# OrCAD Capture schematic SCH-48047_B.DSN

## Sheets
1 Title Page: title: FRDM-KE17Z; rev: B; company: NXP Semiconductors; note: SCH-48047 PDF: SPF-48047; note: 6501 William Cannon Drive West; note: Austin, TX 78735-8598
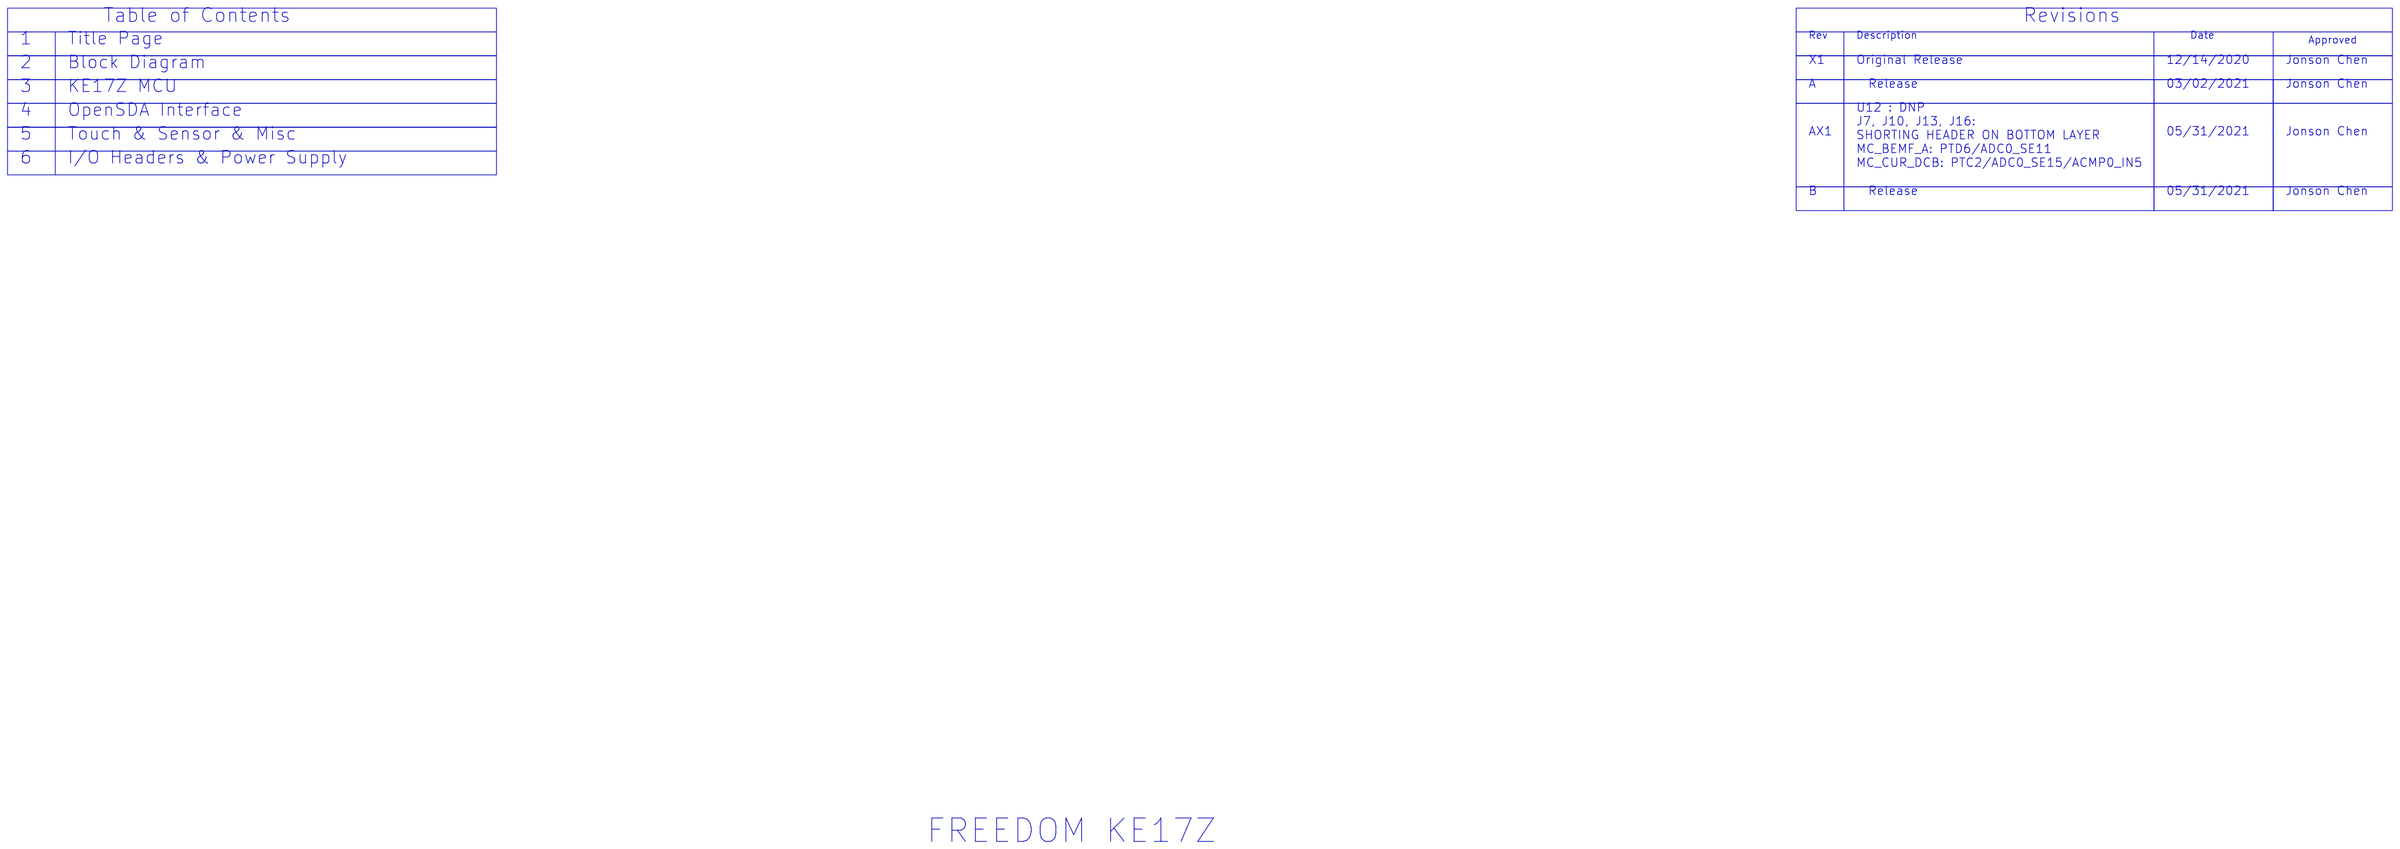
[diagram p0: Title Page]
2 Block Diagram
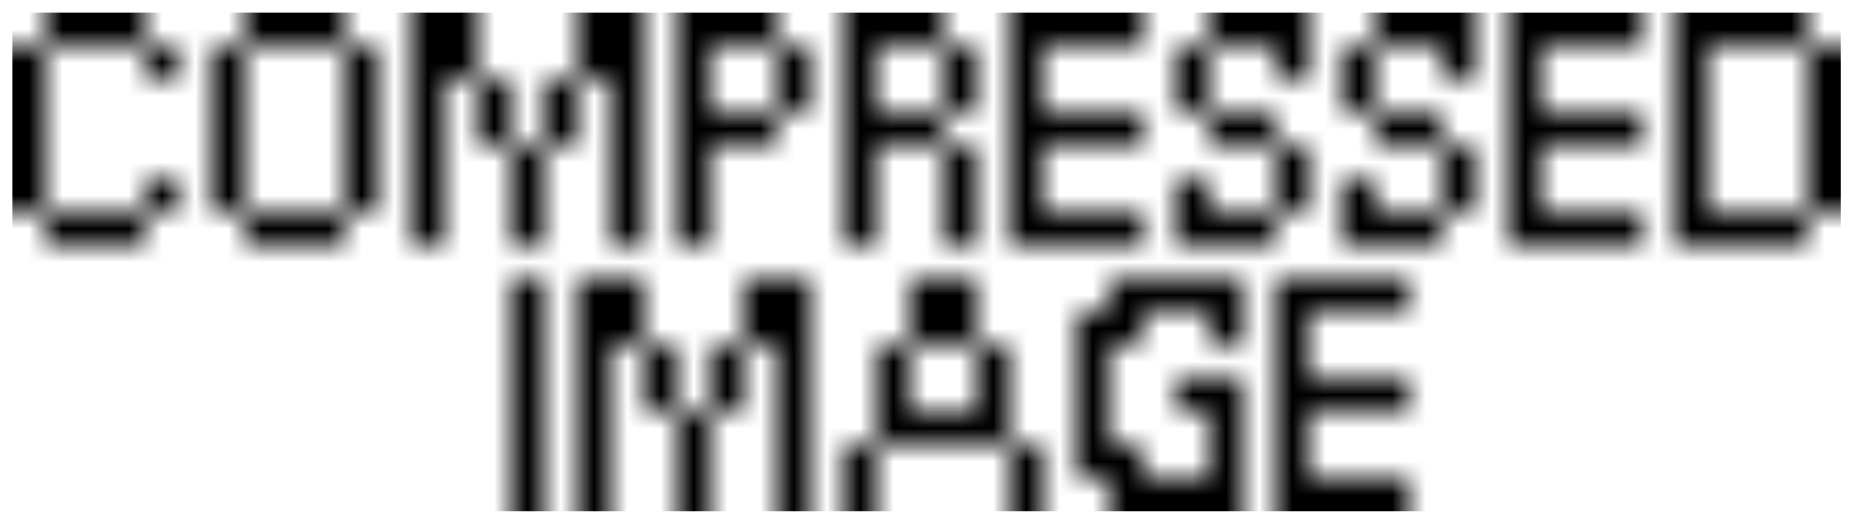
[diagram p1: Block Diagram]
3 KE17Z MCU: size C
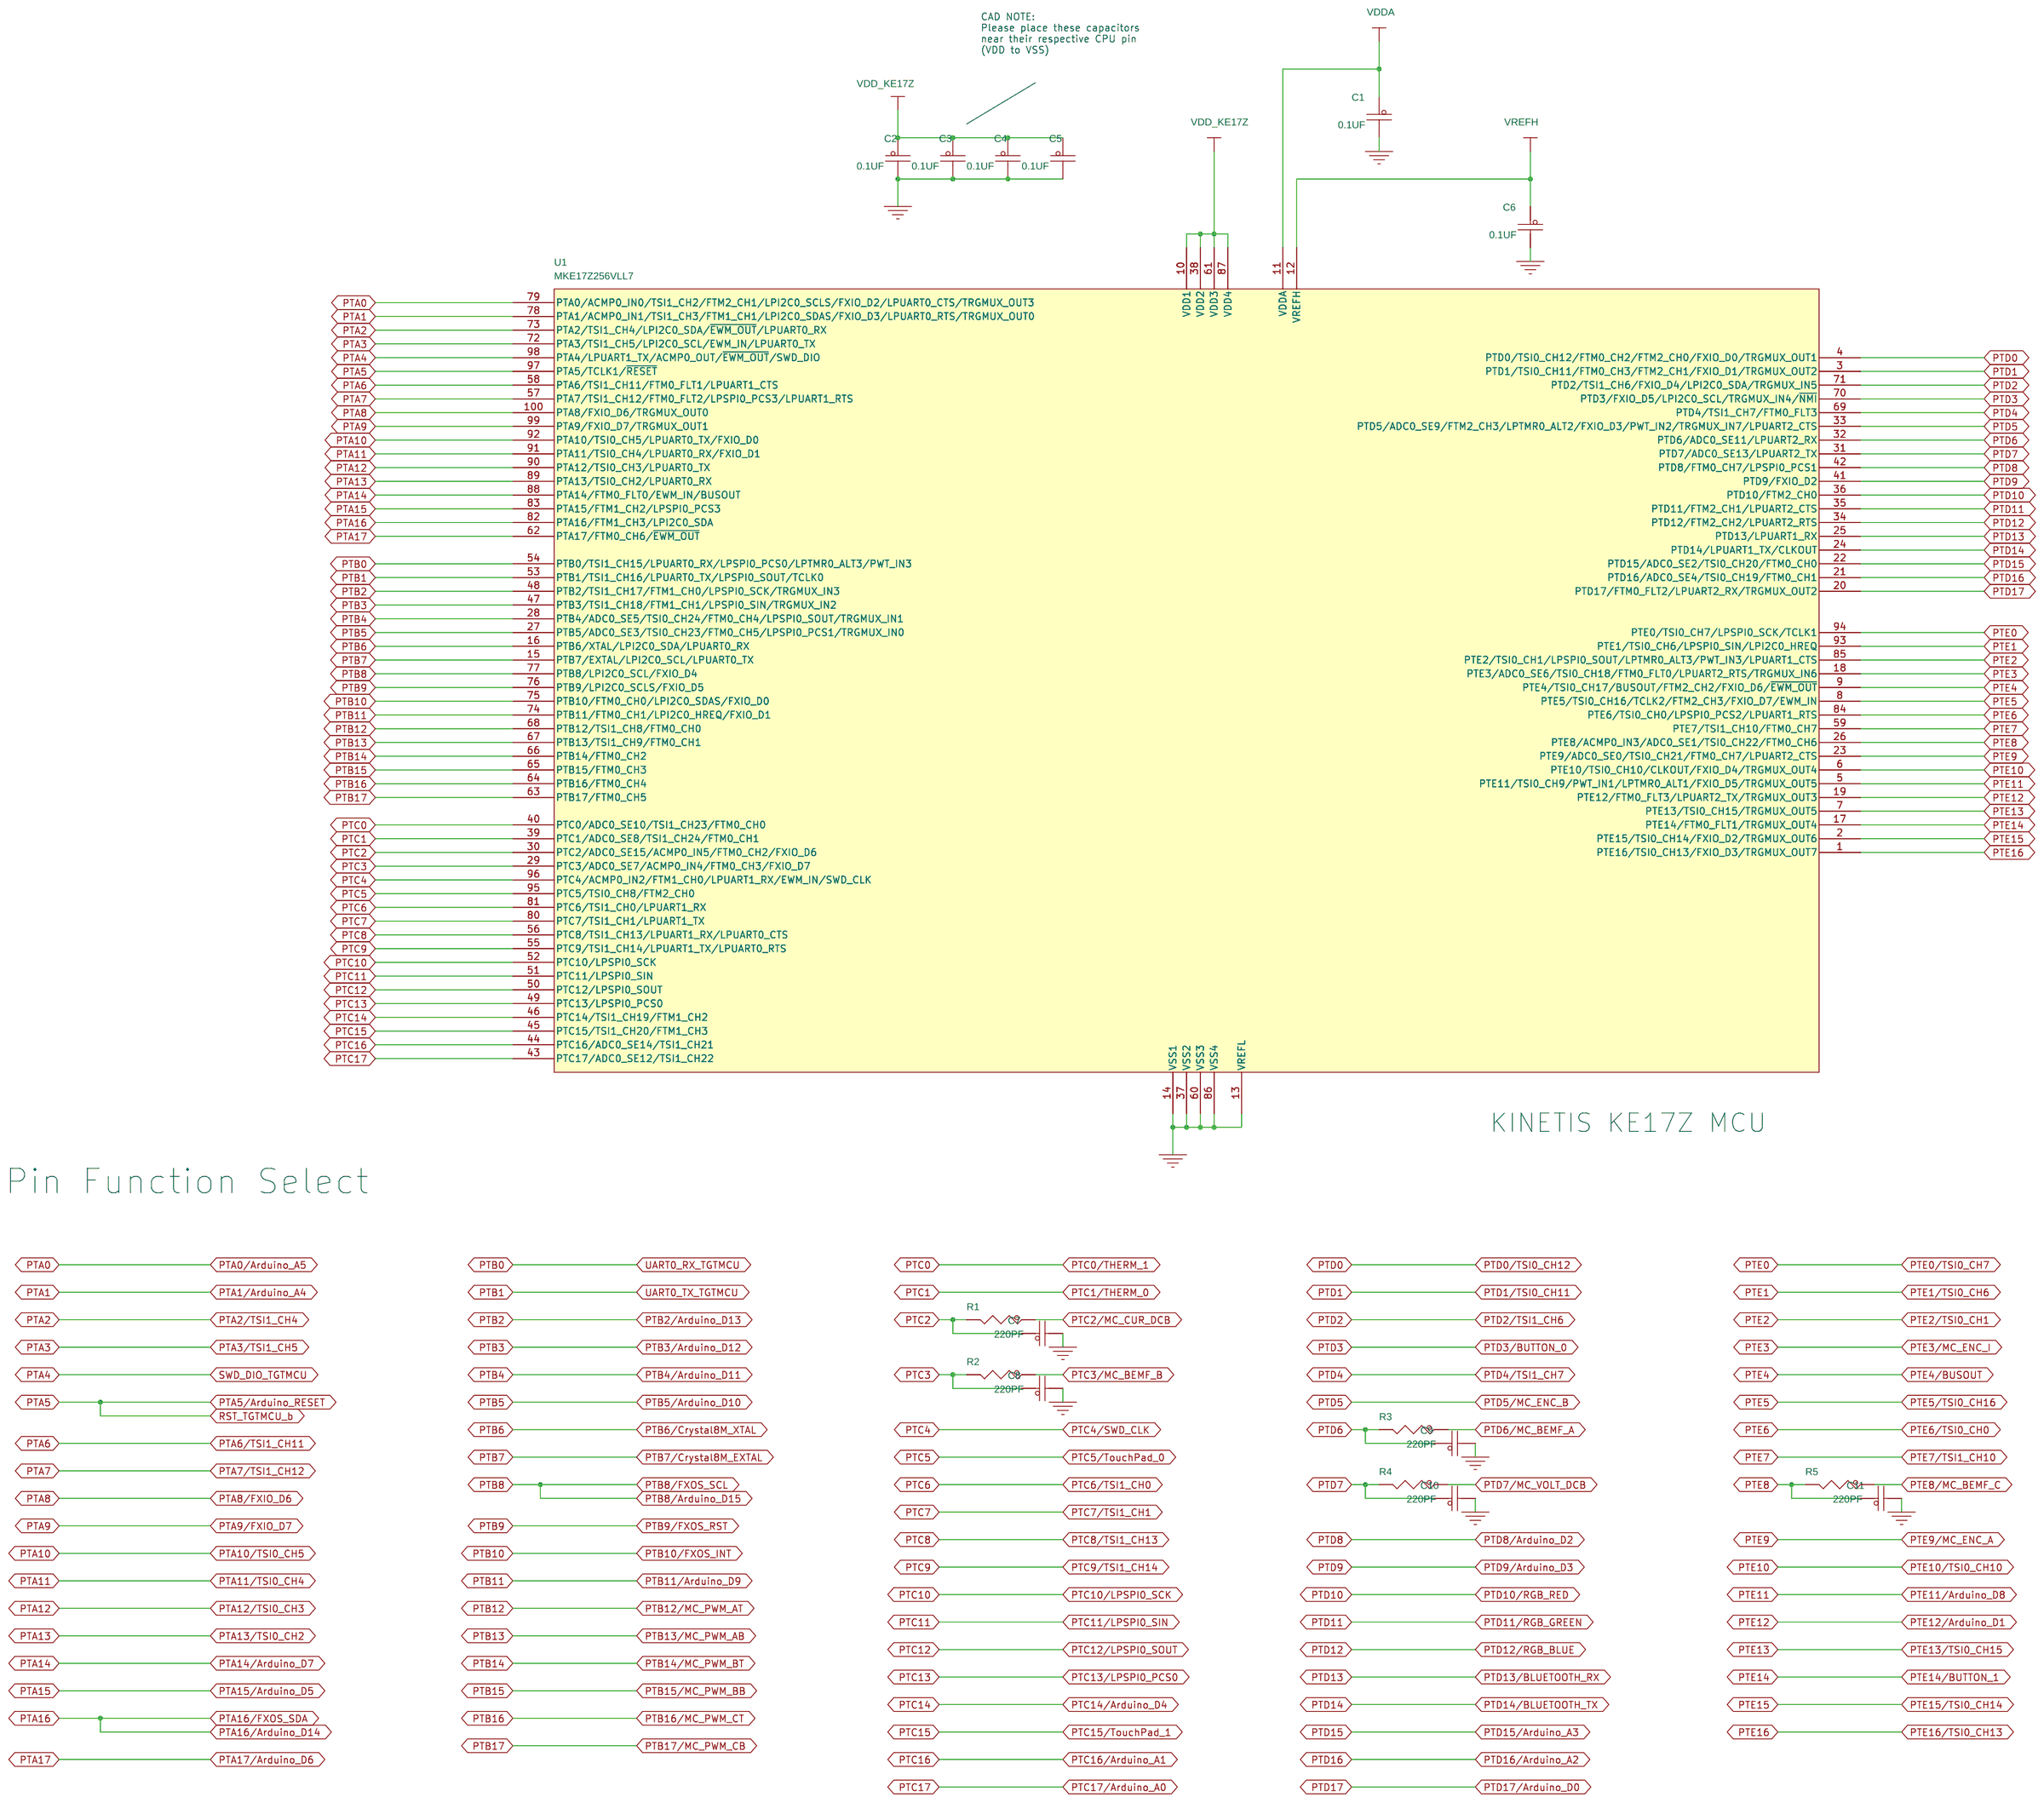
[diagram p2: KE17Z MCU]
4 OpenSDA: size D
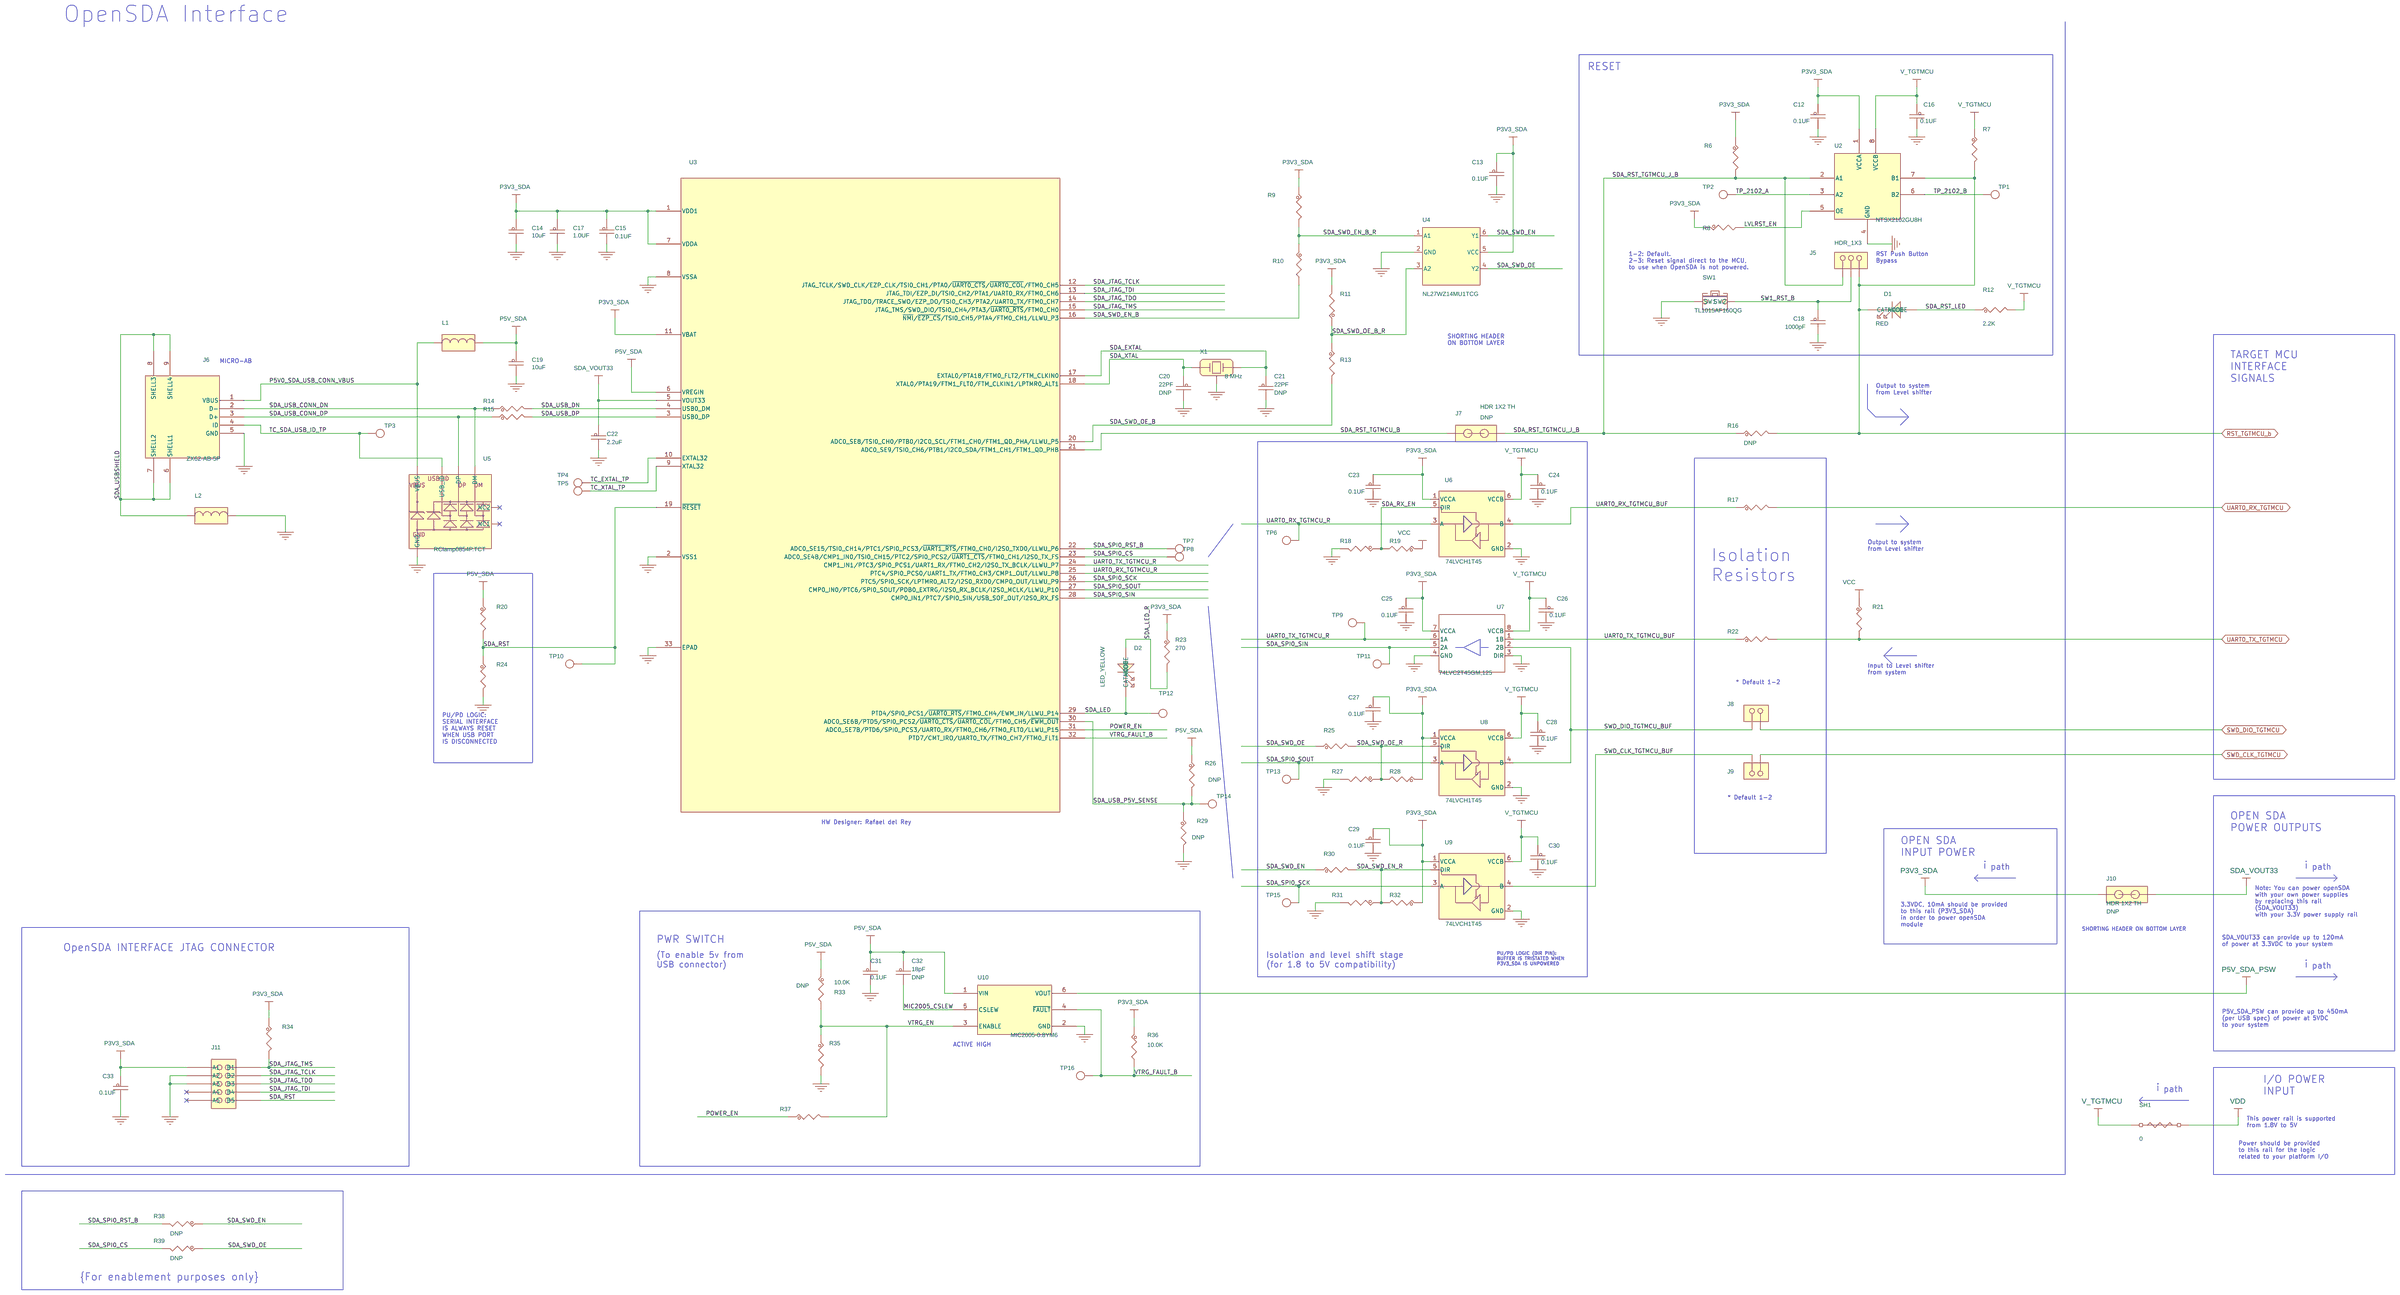
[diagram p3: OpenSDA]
5 Touch & Sensors & Misc: size C
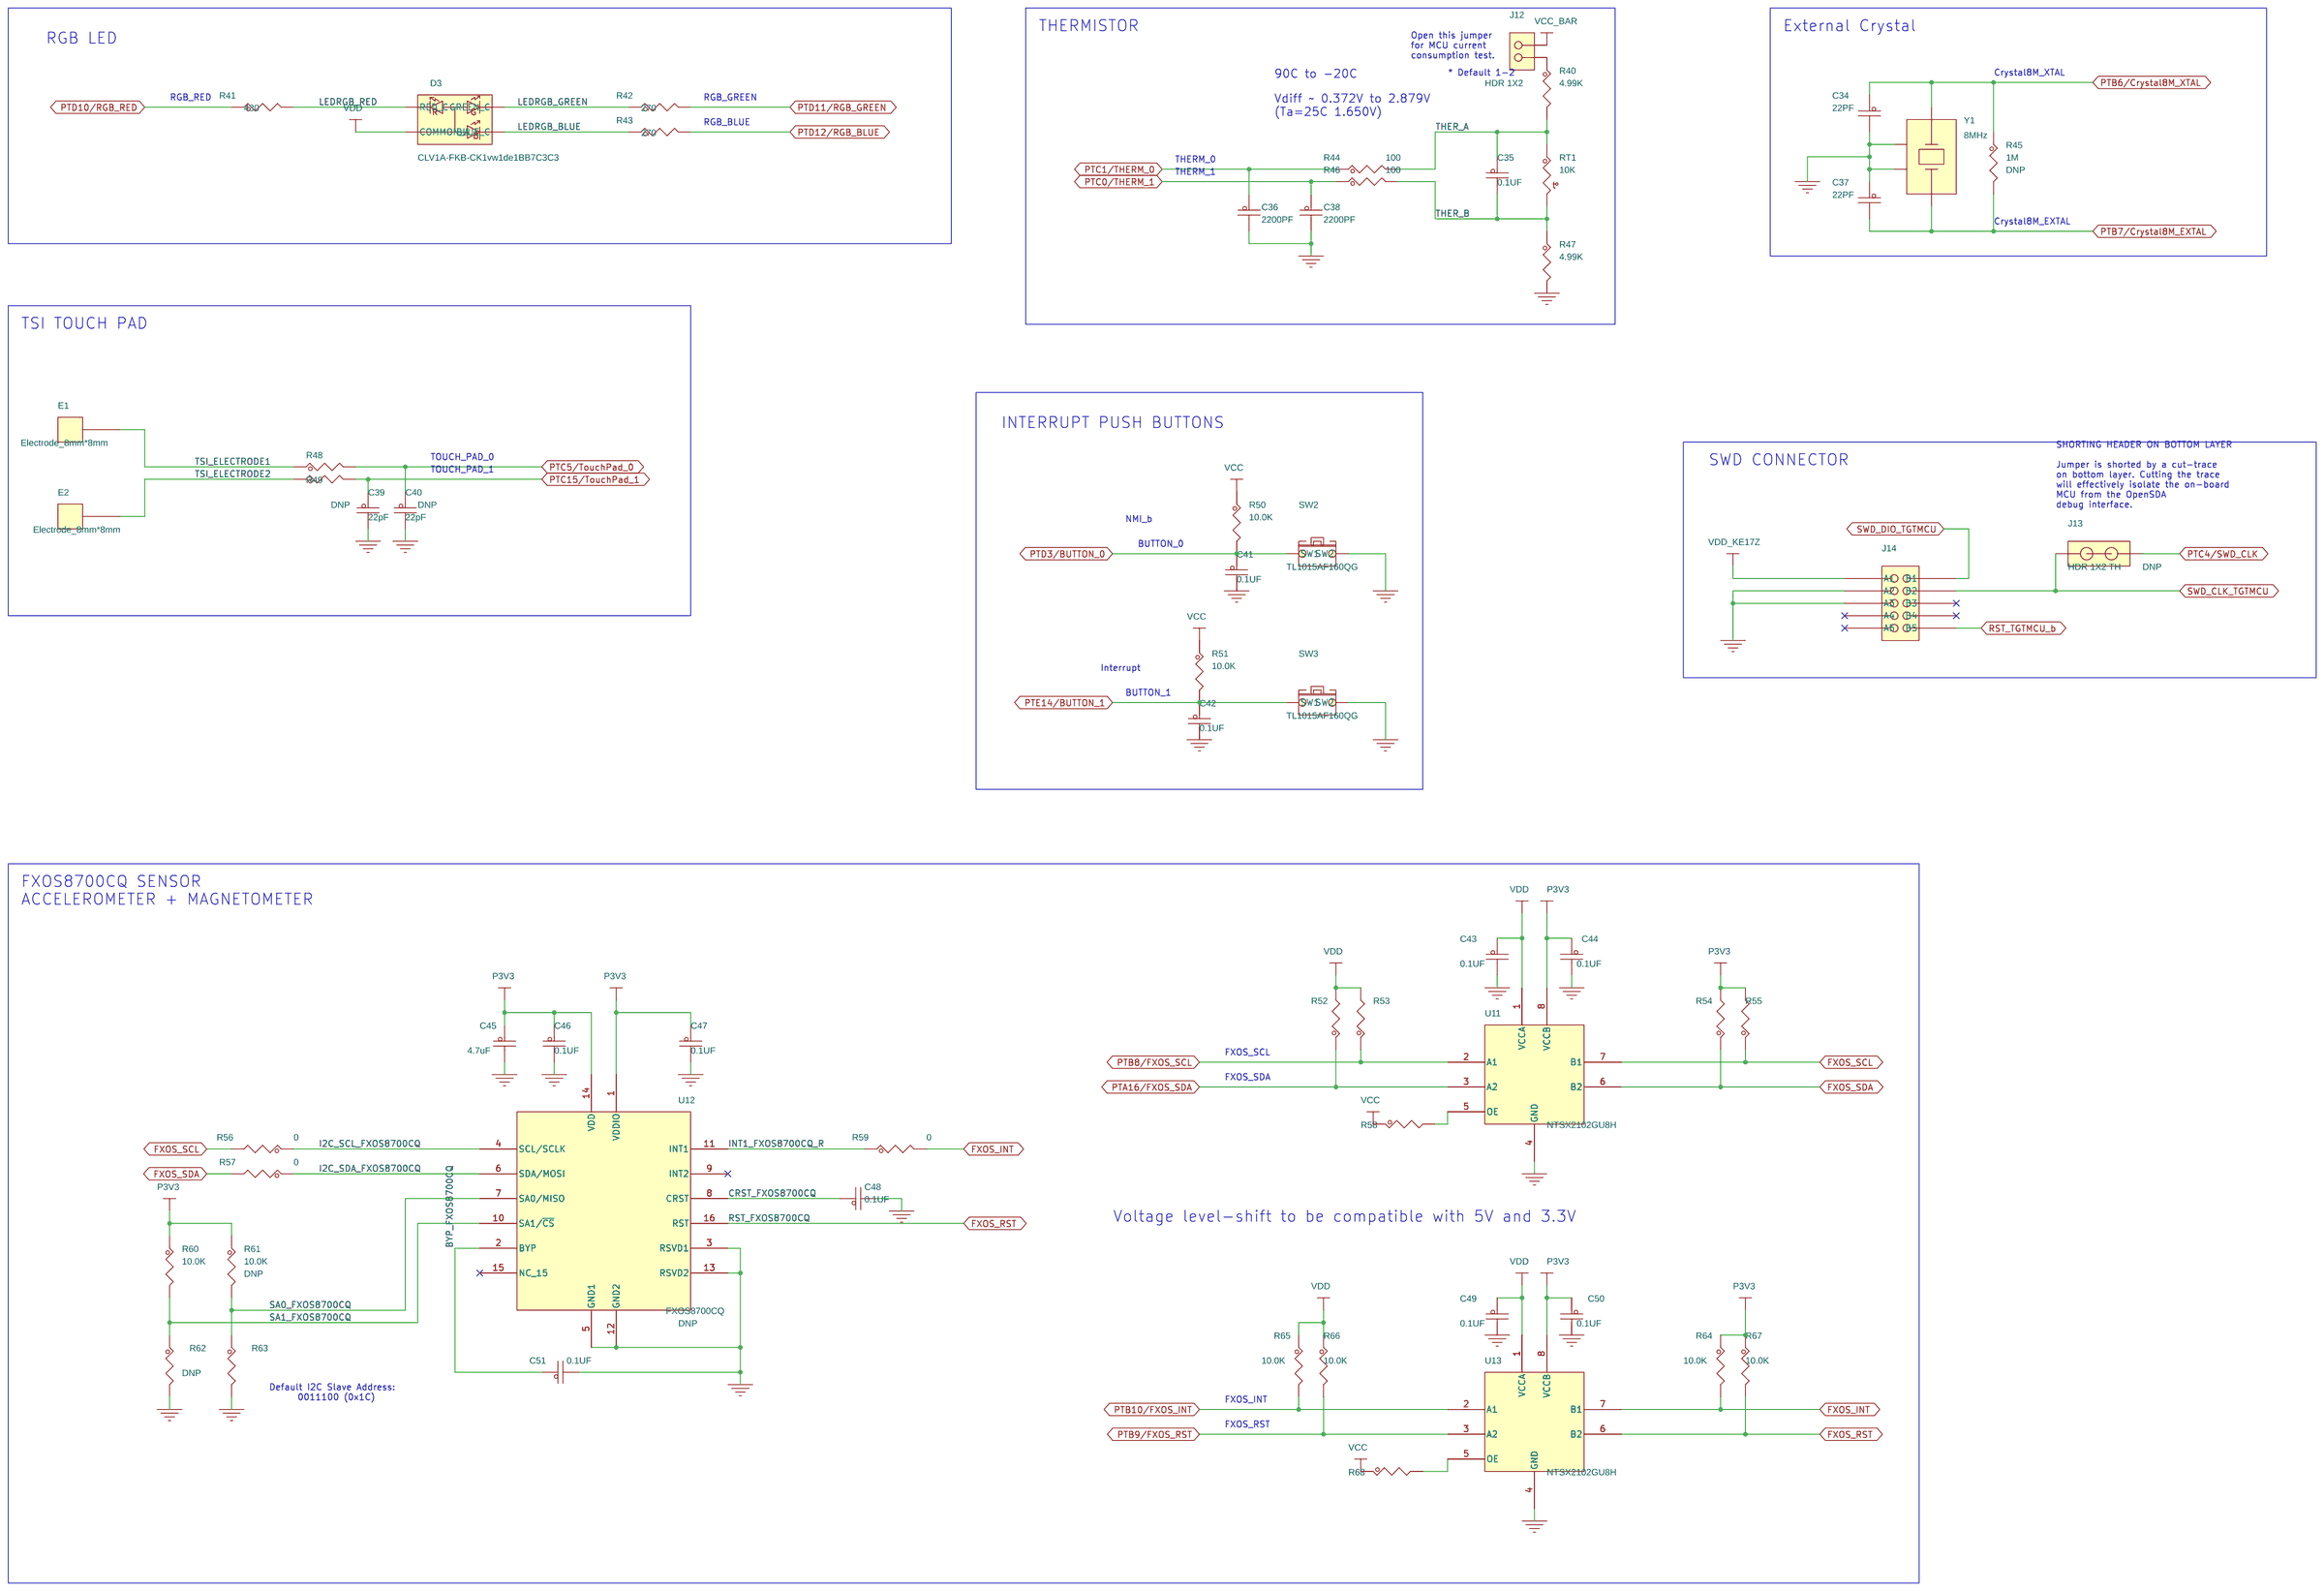
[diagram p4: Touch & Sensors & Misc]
6 I/O Headers & Power Supply: size C
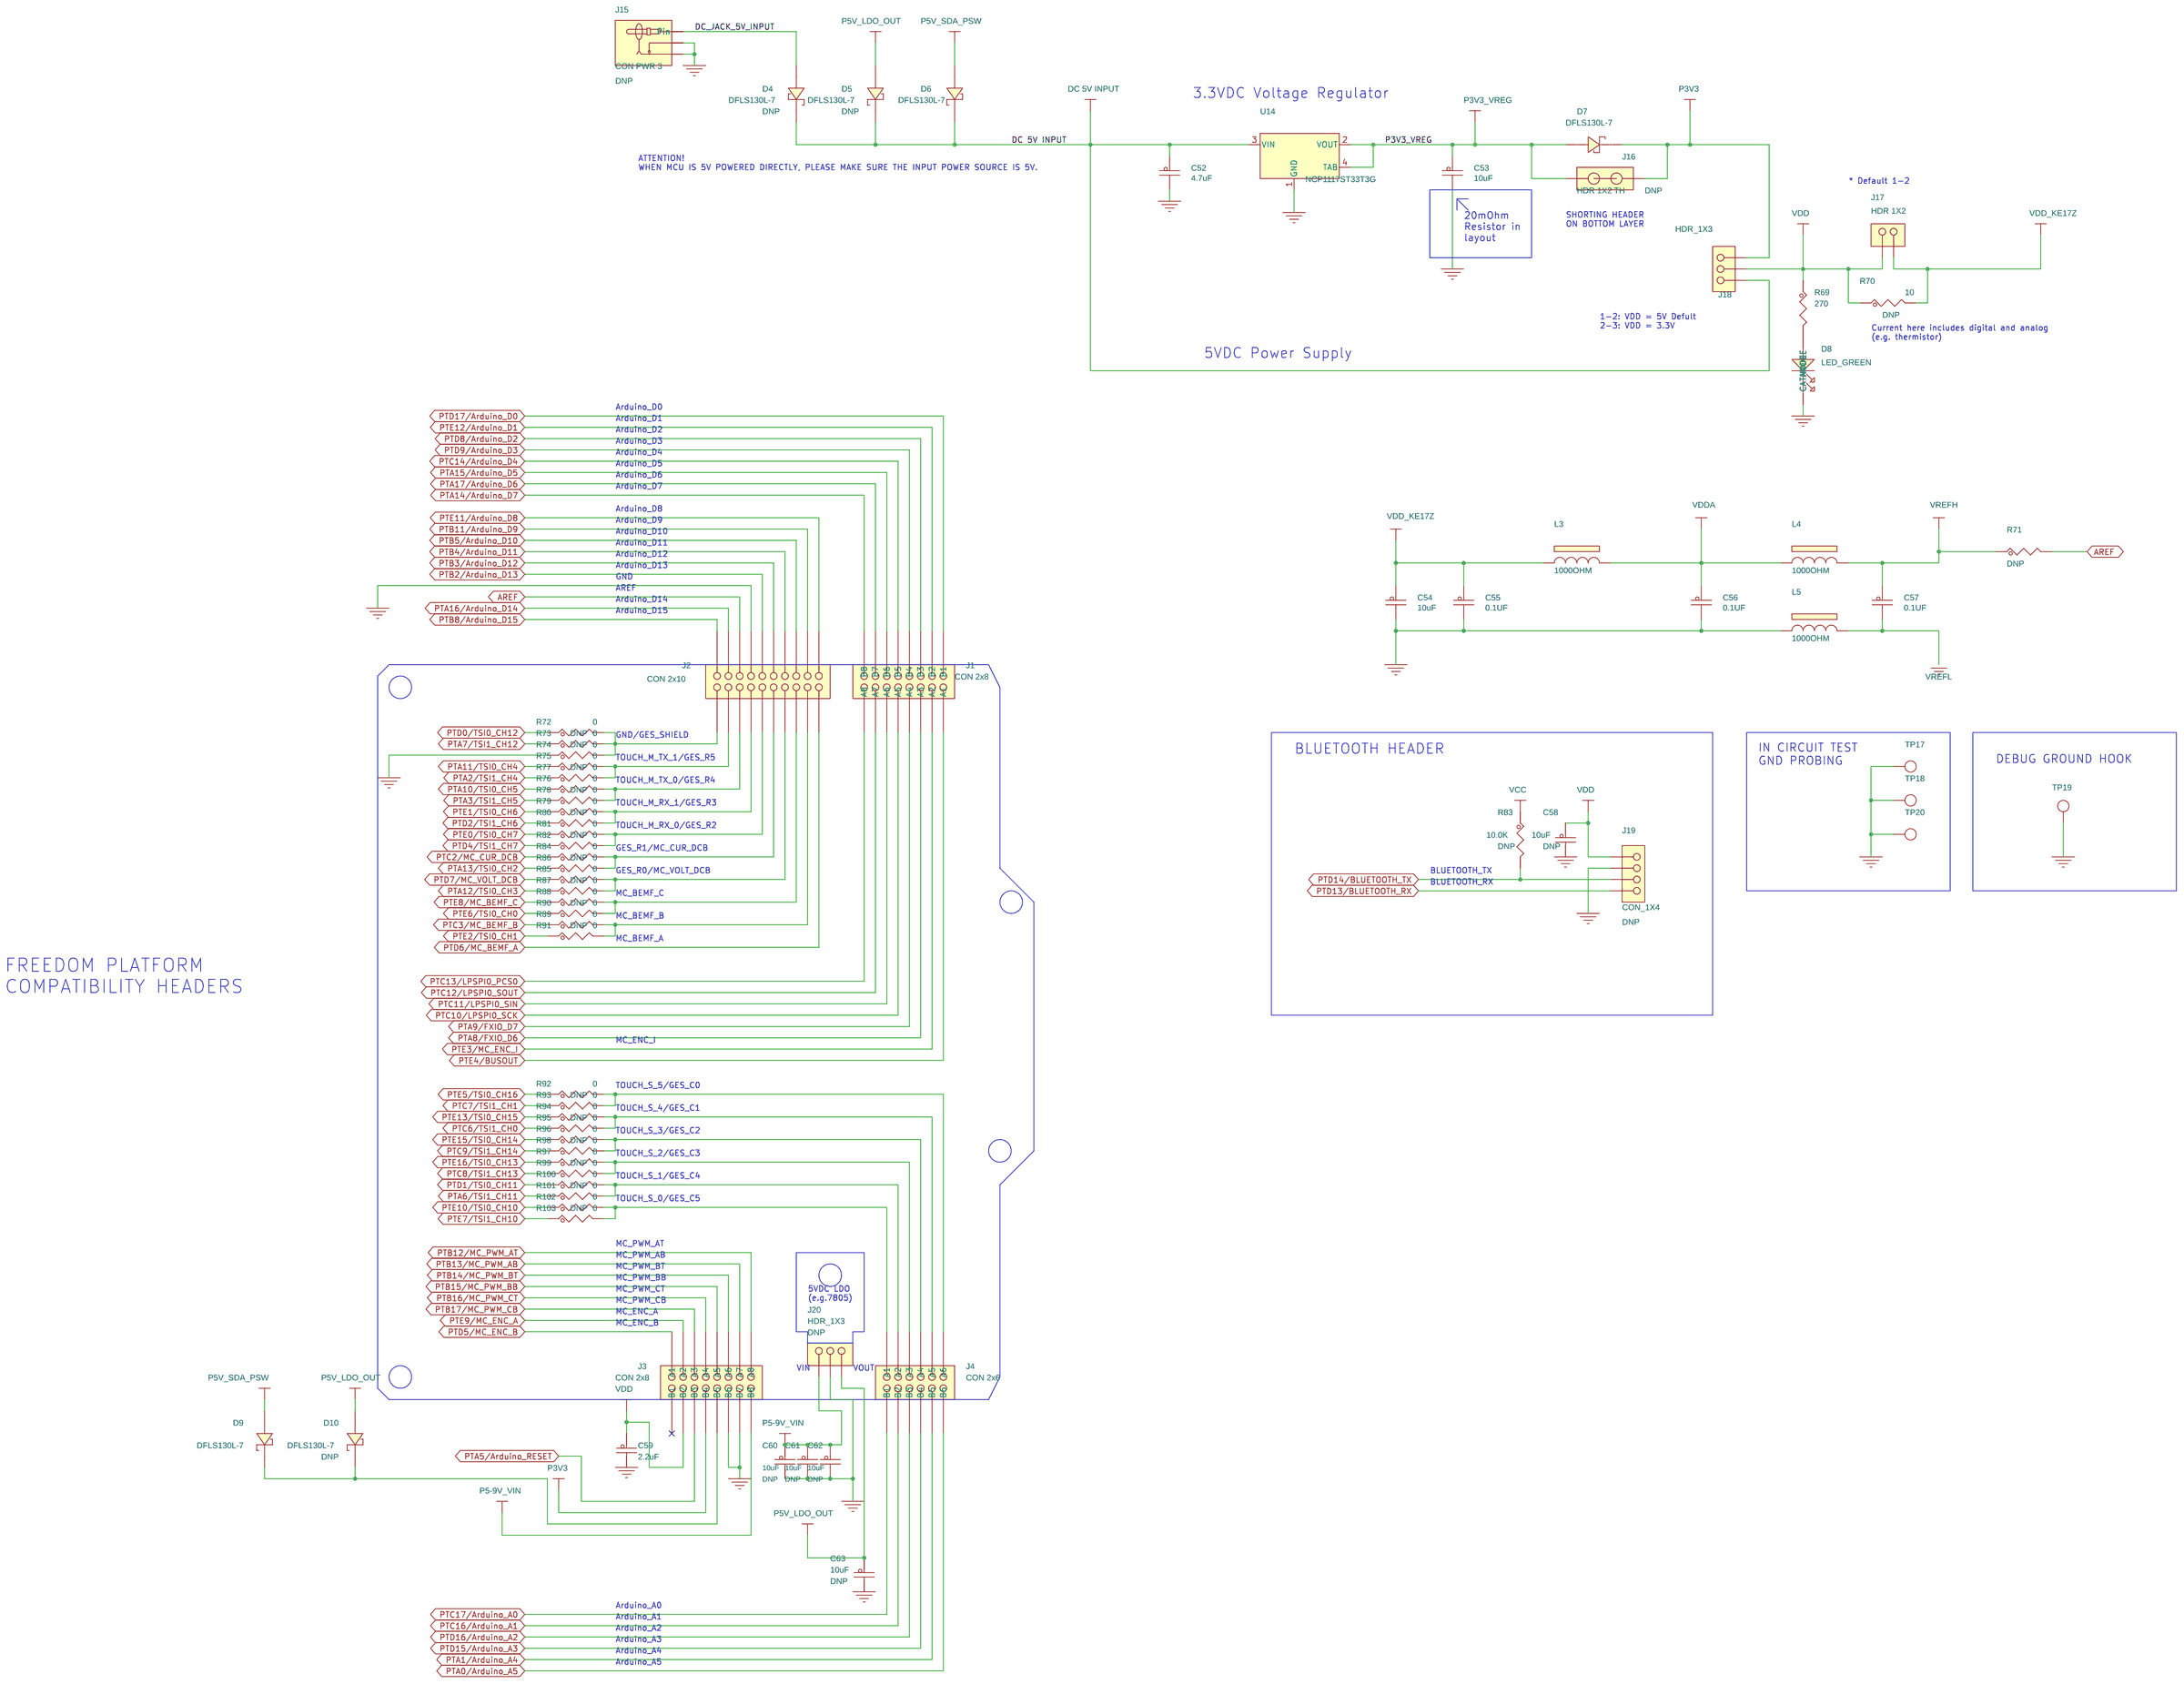
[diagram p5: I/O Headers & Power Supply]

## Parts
sheet I/O Headers & Power Supply
C52  4.7uF  [CC0603_OV]
C53  10uF  [CC0603_OV]
C54  10uF  [CC0603_OV]
C55  0.1UF  [CC0402_25]
C56  0.1UF  [CC0402_25]
C57  0.1UF  [CC0402_25]
C58  10uF  [CC0603_OV]
C59  2.2uF  [CC0603_OV]
C60  10uF  [CC0603_OV]
C61  10uF  [CC0603_OV]
C62  10uF  [CC0603_OV]
C63  10uF  [CC0603_OV]
D4  DFLS130L-7  [powerdi-123_3mmx2mm]
D5  DFLS130L-7  [powerdi-123_3mmx2mm]
D6  DFLS130L-7  [powerdi-123_3mmx2mm]
D7  DFLS130L-7  [powerdi-123_3mmx2mm]
D8  LED_GREEN  [LED_0603]
D9  DFLS130L-7  [powerdi-123_3mmx2mm]
D10  DFLS130L-7  [powerdi-123_3mmx2mm]
J1  CON 2x8  [con_2x8_skt_100_th]
J2  CON 2x10  [con_skt2x10_th]
J3  CON 2x8  [con_2x8_skt_100_th]
J4  CON 2x6  [con_skt2x6_th]
J15  CON PWR 3  [con_jack_pj1_022_th-ra]
J16  HDR 1X2 TH  [SH_HDR102_BOTTOM]
J17  HDR 1X2  [HDR102]
J18  HDR_1X3  [HDR103]
J19  CON_1X4  [con1x4_100_th_ra]
J20  HDR_1X3  [HDR103]
L3  1000OHM  [IND_0603]
L4  1000OHM  [IND_0603]
L5  1000OHM  [IND_0603]
R69  270  [RC0402_25]
R70  10  [RC0603_OV]
R71  0  [RC0402_25]
R72  0  [RC0402_25]
R73  0  [RC0402_25]
R74  0  [RC0402_25]
R75  0  [RC0402_25]
R76  0  [RC0402_25]
R77  0  [RC0402_25]
R78  0  [RC0402_25]
R79  0  [RC0402_25]
R80  0  [RC0402_25]
R81  0  [RC0402_25]
R82  0  [RC0402_25]
R83  10.0K  [RC0402_25]
R84  0  [RC0402_25]
R85  0  [RC0402_25]
R86  0  [RC0402_25]
R87  0  [RC0402_25]
R88  0  [RC0402_25]
R89  0  [RC0402_25]
R90  0  [RC0402_25]
R91  0  [RC0402_25]
R92  0  [RC0402_25]
R93  0  [RC0402_25]
R94  0  [RC0402_25]
R95  0  [RC0402_25]
R96  0  [RC0402_25]
R97  0  [RC0402_25]
R98  0  [RC0402_25]
R99  0  [RC0402_25]
R100  0  [RC0402_25]
R101  0  [RC0402_25]
R102  0  [RC0402_25]
R103  0  [RC0402_25]
TP17  TPAD_030  [TPAD_030]
TP18  TPAD_030  [TPAD_030]
TP19  TEST POINT WHITE  [TEST_LOOP]
TP20  TPAD_030  [TPAD_030]
U14  NCP1117ST33T3G  [sot223]
sheet KE17Z MCU
C1  0.1UF  [CC0603_OV]
C2  0.1UF  [CC0402_25]
C3  0.1UF  [CC0402_25]
C4  0.1UF  [CC0402_25]
C5  0.1UF  [CC0402_25]
C6  0.1UF  [CC0603_OV]
C7  220PF  [CC0402_25]
C8  220PF  [CC0402_25]
C9  220PF  [CC0402_25]
C10  220PF  [CC0402_25]
C11  220PF  [CC0402_25]
R1  100  [RC0402_25]
R2  100  [RC0402_25]
R3  100  [RC0402_25]
R4  100  [RC0402_25]
R5  100  [RC0402_25]
U1  MKE17Z256VLL7  [lqfp100_0p5_14x14]
sheet OpenSDA
C12  0.1UF  [CC0402_25]
C13  0.1UF  [CC0402_25]
C14  10uF  [CC0603_OV]
C15  0.1UF  [CC0402_25]
C16  0.1UF  [CC0402_25]
C17  1.0UF  [CC0402_25]
C18  1000pF  [CC0402_25]
C19  10uF  [CC0603_OV]
C20  22PF  [CC0402_25]
C21  22PF  [CC0402_25]
C22  2.2uF  [CC0603_OV]
C23  0.1UF  [CC0402_25]
C24  0.1UF  [CC0402_25]
C25  0.1UF  [CC0402_25]
C26  0.1UF  [CC0402_25]
C27  0.1UF  [CC0402_25]
C28  0.1UF  [CC0402_25]
C29  0.1UF  [CC0402_25]
C30  0.1UF  [CC0402_25]
C31  0.1UF  [CC0402_25]
C32  18pF  [CC0402_25]
C33  0.1UF  [CC0402_25]
D1  RED  [LED_0603]
D2  LED_YELLOW  [LED_0603]
J5  HDR_1X3  [HDR103]
J6  ZX62-AB-5P  [MICRO_USB_CONN_9PIN]
J7  HDR 1X2 TH  [SH_HDR102_BOTTOM]
J8  HDR 1X2  [HDR102]
J9  HDR 1X2  [HDR102]
J10  HDR 1X2 TH  [SH_HDR102_BOTTOM]
J11  HDR 2X5  [hdr_5X2_ftsh_th_nsp]
L1  330 OHM  [IND_0805]
L2  330 OHM  [IND_0805]
R6  10.0K  [RC0402_25]
R7  10.0K  [RC0402_25]
R8  4.7K  [RC0402_25]
R9  10.0K  [RC0402_25]
R10  0  [RC0402_25]
R11  10.0K  [RC0402_25]
R12  2.2K  [RC0402_25]
R13  0  [RC0402_25]
R14  33  [RC0402_25]
R15  33  [RC0402_25]
R16  0  [RC0402_25]
R17  1.0K  [RC0402_25]
R18  10.0K  [RC0402_25]
R19  4.7K  [RC0402_25]
R20  4.7K  [RC0402_25]
R21  10.0K  [RC0402_25]
R22  1.0K  [RC0402_25]
R23  270  [RC0402_25]
R24  10.0K  [RC0402_25]
R25  0  [RC0402_25]
R26  4.7K  [RC0402_25]
R27  10.0K  [RC0402_25]
R28  4.7K  [RC0402_25]
R29  10.0K  [RC0402_25]
R30  0  [RC0402_25]
R31  10.0K  [RC0402_25]
R32  4.7K  [RC0402_25]
R33  10.0K  [RC0402_25]
R34  10.0K  [RC0402_25]
R35  15K  [RC0402_25]
R36  10.0K  [RC0402_25]
R37  1.0K  [RC0402_25]
R38  0  [RC0402_25]
R39  0  [RC0402_25]
SH1  0  [SH0603]
SW1  TL1015AF160QG  [sw2_spst_4x3_sm_f]
TP1  TPAD_030  [TPAD_030]
TP2  TPAD_030  [TPAD_030]
TP3  TPAD_030  [TPAD_030]
TP4  TPAD_030  [TPAD_030]
TP5  TPAD_030  [TPAD_030]
TP6  TPAD_030  [TPAD_030]
TP7  TPAD_030  [TPAD_030]
TP8  TPAD_030  [TPAD_030]
TP9  TPAD_030  [TPAD_030]
TP10  TPAD_030  [TPAD_030]
TP11  TPAD_030  [TPAD_030]
TP12  TPAD_030  [TPAD_030]
TP13  TPAD_030  [TPAD_030]
TP14  TPAD_030  [TPAD_030]
TP15  TPAD_030  [TPAD_030]
TP16  TPAD_030  [TPAD_030]
U2  NTSX2102GU8H  [xqfn8_1p45x1p25mm]
U3  MK20DX128VFM5  [QFN32_S142EP]
U4  NL27WZ14MU1TCG  [udfn6_1p45x1_0p5mm]
U5  RClamp0854P.TCT  [slp1616p6]
U6  74LVCH1T45  [udfn6_1x1p5mm]
U7  74LVC2T45GM,125  [qfn8_1p6x1p6mm]
U8  74LVCH1T45  [udfn6_1x1p5mm]
U9  74LVCH1T45  [udfn6_1x1p5mm]
U10  MIC2005-0.8YM6  [SOT23-6_a]
X1  8 MHz  [XTAL3_3P35X1P45_SM]
sheet Touch & Sensors & Misc
C34  22PF  [CC0402_25]
C35  0.1UF  [CC0402_25]
C36  2200PF  [CC0402_25]
C37  22PF  [CC0402_25]
C38  2200PF  [CC0402_25]
C39  22pF  [CC0402_25]
C40  22pF  [CC0402_25]
C41  0.1UF  [CC0402_25]
C42  0.1UF  [CC0402_25]
C43  0.1UF  [CC0402_25]
C44  0.1UF  [CC0402_25]
C45  4.7uF  [cc0402_tol0p15]
C46  0.1UF  [CC0402_25]
C47  0.1UF  [CC0402_25]
C48  0.1UF  [CC0402_25]
C49  0.1UF  [CC0402_25]
C50  0.1UF  [CC0402_25]
C51  0.1UF  [CC0402_25]
D3  CLV1A-FKB-CK1vw1de1BB7C3C3  [led4_3p4x3mm_smt]
E1  Electrode_8mm*8mm  [electrode_8mm_sq_cir]
E2  Electrode_8mm*8mm  [electrode_8mm_sq_cir]
J12  HDR 1X2  [HDR102]
J13  HDR 1X2 TH  [SH_HDR102_BOTTOM]
J14  HDR 2X5  [hdr_5X2_ftsh_th_nsp]
R40  4.99K  [RC0603_OV]
R41  430  [RC0402_25]
R42  270  [RC0402_25]
R43  270  [RC0402_25]
R44  100  [RC0402_25]
R45  1M  [RC0402_25]
R46  100  [RC0402_25]
R47  4.99K  [RC0603_OV]
R48  0  [RC0402_25]
R49  0  [RC0402_25]
R50  10.0K  [RC0402_25]
R51  10.0K  [RC0402_25]
R52  4.7K  [RC0402_25]
R53  4.7K  [RC0402_25]
R54  4.7K  [RC0402_25]
R55  4.7K  [RC0402_25]
R56  0  [RC0603_OV]
R57  0  [RC0603_OV]
R58  4.7K  [RC0402_25]
R59  0  [RC0402_25]
R60  10.0K  [RC0402_25]
R61  10.0K  [RC0402_25]
R62  4.7K  [RC0402_25]
R63  4.7K  [RC0402_25]
R64  10.0K  [RC0402_25]
R65  10.0K  [RC0402_25]
R66  10.0K  [RC0402_25]
R67  10.0K  [RC0402_25]
R68  4.7K  [RC0402_25]
RT1  10K  [RC0603_OV]
SW2  TL1015AF160QG  [sw2_spst_4x3_sm_f]
SW3  TL1015AF160QG  [sw2_spst_4x3_sm_f]
U11  NTSX2102GU8H  [xqfn8_1p45x1p25mm]
U12  FXOS8700CQ  [QFN5X3_0P5_3X3]
U13  NTSX2102GU8H  [xqfn8_1p45x1p25mm]
Y1  8MHz  [xtal4_5x3]

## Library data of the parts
C52 = CAP_NP: CAP CER 4.7uF 10V 10% X7S 0603; AGILE_PN: 150-79499; CAD_APPROVED: Yes; FPLIST: CC0603_OV,CC0603,0603_CC; HEIGHT: 0.95 MM; MFG_NAME01: murata; MFG_PN01: GRM188C71A475KE11D; ROHS: Yes; Tolerance: 10%; VOLTAGE: 10V
C14 C19 C53 = CAP_NP: CAP CER 10UF 10V 10% X5R 0603; AGILE_PN: 150-78675; CAD_APPROVED: Yes; FPLIST: CC0603_OV,CC0603,0603_CC; HEIGHT: 1.016MM; MFG_NAME01: MURATA; MFG_PN01: GRM188R61A106KE69D; ROHS: Yes; Temp Range: -55°C ~ 85°C; Temp_Range: -55°C ~ 85°C; Tolerance: 10%; VOLTAGE: 10v
C54 = CAP_NP: CAP CER 10UF 10V 10% X5R 0603; AGILE_PN: 150-78675; CAD_APPROVED: Yes; FPLIST: CC0805_OV,CC0805,0805_CC; HEIGHT: 1.016MM; MFG_NAME01: MURATA; MFG_PN01: GRM188R61A106KE69D; ROHS: Yes; TOL: 10%; Temp Range: -55°C ~ 85°C; Temp_Range: -55°C ~ 85°C; Tolerance: 10%; VOLTAGE: 10v
C35 C41 C42 C46-C48 C51 C55-C57 = CAP_NP: CAP CER 0.1UF 10V 10% X5R 0402; AGILE_PN: 150-75634; CAD_APPROVED: Yes; FPLIST: CC0402_25,CC0402_HD,0402_CC; HEIGHT: 0.64MM; MFG_NAME01: YAGEO AMERICA; MFG_PN01: CC0402KRX5R6BB104; Package Size: 0402; ROHS: Yes; Tolerance: 10%; VOLTAGE: 10V
C58 = CAP_NP: CAP CER 10UF 10V 10% X5R 0603; AGILE_PN: 150-78675; ASSY_OPT: DNP; CAD_APPROVED: Yes; FPLIST: CC0805_OV,CC0805,0805_CC; HEIGHT: 1.016MM; MFG_NAME01: MURATA; MFG_PN01: GRM188R61A106KE69D; ROHS: Yes; TOL: 10%; Temp Range: -55°C ~ 85°C; Temp_Range: -55°C ~ 85°C; Tolerance: 10%; VOLTAGE: 10v
C22 C59 = CAP_NP: CAP CER 2.2UF 6.3V 10% X5R 0603; AGILE_PN: 150-76330; CAD_APPROVED: Yes; FPLIST: CC0603_OV,CC0603,0603_CC; HEIGHT: 0.9MM; MFG_NAME01: KEMET; MFG_PN01: C0603C225K9PAC; Package Size: 0603; Package Type: Tape&reel; ROHS: Yes; Tolerance: 10%; VOLTAGE: 6.3V
C60-C63 = CAP_NP: CAP CER 10UF 10V 10% X5R 0603; AGILE_PN: 150-78675; ASSY_OPT: DNP; CAD_APPROVED: Yes; FPLIST: CC0603_OV,CC0603,0603_CC; HEIGHT: 1.016MM; MFG_NAME01: MURATA; MFG_PN01: GRM188R61A106KE69D; ROHS: Yes; Temp Range: -55°C ~ 85°C; Temp_Range: -55°C ~ 85°C; Tolerance: 10%; VOLTAGE: 10v
D4 D5 D10 = DIODE_SCHTKY: DIODE SCH 1A 30V PowerDI123; AGILE_PN: 480-78285; ASSY_OPT: DNP; CAD_APPROVED: Yes; HEIGHT: 1MM; MFG_NAME01: DIODES INC; ROHS: Yes; Rated Voltage: 30V
D6 D7 D9 = DIODE_SCHTKY: DIODE SCH 1A 30V PowerDI123; AGILE_PN: 480-78285; CAD_APPROVED: Yes; HEIGHT: 1MM; MFG_NAME01: DIODES INC; ROHS: Yes; Rated Voltage: 30V
D8 = LED: LED ULTRA-BRIGHT GREEN SMT 0603; AGILE_PN: 370-75077; CAD_APPROVED: YES; HEIGHT: 0.8MM; MFG_NAME01: LITE ON; MFG_PN01: LTST-C190KGKT; ROHS: Yes; Rated Voltage: 2V; VOLTAGE: 2V
J1 J3 = CONN_HDR_8X2: CON 2X8 SKT SHRD TH 100MIL CTR 345H AU 126L; 3D_Mechanical_Footprint_File: ftp://fcl.am.freescale.net/ALLEGRO/step/con_2x8_skt_100_th.STEP; AGILE_PN: 210-81775; CAD_APPROVED: Yes; HEIGHT: 8.75MM; MFG_NAME01: ANYTRONIC CORPORATION LIMITED; MFG_PN01: 08010S31611-29RF; ROHS: Yes; Temp Range: -40 to +105C
J2 = CONN_HDR_10X2: CON 2X10 SKT SHRD TH 100MIL CTR 345H AU 126L; 3D_Mechanical_Footprint_File: ftp://fcl.am.freescale.net/ALLEGRO/step/con_skt2x10_th.STEP; AGILE_PN: 210-81776; CAD_APPROVED: Yes; HEIGHT: 8.75MM; MFG_NAME01: ANYTRONIC CORPORATION LIMITED; MFG_PN01: 08010S32011-29RF; ROHS: Yes; Temp Range: -40 to +105C; Temp_Range: -40 to +105C
J4 = CONN_HDR_6X2: CON 2X6 SKT SHRD TH 100MIL CTR 345H AU 126L; 3D_Mechanical_Footprint_File: ftp://fcl.am.freescale.net/ALLEGRO/step/con_skt2x6_th_126l.STEP; AGILE_PN: 210-81774; CAD_APPROVED: Yes; HEIGHT: 8.75MM; MFG_NAME01: ANYTRONIC CORPORATION LIMITED; MFG_PN01: 08010S31211-29RF; ROHS: Yes; Temp Range: -40 to +105C; Temp_Range: -40 to +105C
J15 = DC_POWER_JACK: CON 3 PWR JACK RA TH --- 201H AG 118L; 3D_Mechanical_Footprint_File: ftp://fcl.am.freescale.net/ALLEGRO/step/con_jack_pj1_022_th-ra.step; AGILE_PN: 210-80316; ASSY_OPT: DNP; CAD_APPROVED: Yes; HEIGHT: 5.1MM; MFG_NAME01: CUI INC; MFG_PN01: PJ1-022; ROHS: Yes
J7 J10 J13 J16 = JUMPER_2FITTED: HDR 1X2 TH 100MIL SP 339H AU 98L; 3D_Mechanical_Footprint_File: ftp://fcl.am.freescale.net/ALLEGRO/step/hdr102_338h.STEP; AGILE_PN: 210-75439; ASSY_OPT: DNP; CAD_APPROVED: YES; FPLIST: hdr102_338h,HDR_1X2,SH_HDR102_BOTTOM; HEIGHT: 8.71 MM; MFG_NAME01: SAMTEC; MFG_PN01: TSW-102-07-G-S; ROHS: Yes; Temp Range: -55°C to +125°C
J12 J17 = CONN_HDR_2X1: HDR 1X2 TH 100MIL SP 339H AU 98L; 3D_Mechanical_Footprint_File: ftp://fcl.am.freescale.net/ALLEGRO/step/hdr102_95l.STEP; AGILE_PN: 210-81490; CAD_APPROVED: Yes; FPLIST: HDR102,SH_HDR102_BOTTOM; HEIGHT: 8.59MM; MFG_NAME01: ANYTRONIC CORPORATION LIMITED; MFG_PN01: 0901S0202011N9T-31RF; ROHS: Yes; Temp Range: -55°C to +105°C; Temp_Range: -55°C to +105°C
J5 J18 = CONN_HDR_3X1: HDR 1X3 TH 100MIL SP 338H AU 98L; 3D_Mechanical_Footprint_File: ftp://fcl.am.freescale.net/ALLEGRO/step/hdr103_330h.STEP; AGILE_PN: 210-81491; CAD_APPROVED: Yes; HEIGHT: 8.59MM; MFG_NAME01: ANYTRONIC CORPORATION LIMITED; MFG_PN01: 0901S0203011N9T-31RF; ROHS: Yes; Temp Range: -55°C to +105°C; Temp_Range: -55°C to +105°C
J19 = CONN_HDR_4X1: CON 1X4 SKT RA SHRD TH 100MIL SP 108H AU 124L; 3D_Mechanical_Footprint_File: ftp://fcl.am.freescale.net/ALLEGRO/step/con1x4_100_th_ra.step; AGILE_PN: 210-80454; ASSY_OPT: DNP; CAD_APPROVED: Yes; HEIGHT: 2.74MM; MFG_NAME01: SULLINS ELECTRONICS CORP; MFG_PN01: PPPC041LGBN-RC; ROHS: Yes
J20 = CONN_HDR_3X1: HDR 1X3 TH 100MIL SP 338H AU 98L; 3D_Mechanical_Footprint_File: ftp://fcl.am.freescale.net/ALLEGRO/step/hdr103_330h.STEP; AGILE_PN: 210-81491; ASSY_OPT: DNP; CAD_APPROVED: Yes; HEIGHT: 8.59MM; MFG_NAME01: ANYTRONIC CORPORATION LIMITED; MFG_PN01: 0901S0203011N9T-31RF; ROHS: Yes; Temp Range: -55°C to +105°C; Temp_Range: -55°C to +105°C
L3-L5 = INDUCTOR_FERRITE: IND FER BEAD 1000OHM@100MHz 0.4A 25% AUTO 0603; AGILE_PN: 180-78126; CAD_APPROVED: Yes; FPLIST: IND_0603,IND0603_CC; HEIGHT: 0.95MM; MFG_NAME01: MURATA; MFG_PN01: BLM18AG102SH1; PART_TYPE: FILTER; Package Size: 0603; ROHS: Yes; Tolerance: 25%
R23 R42 R43 R69 = RES: RES MF 270 OHM 1/10W 1% AEC-Q200 0402; AGILE_PN: 470-30782; CAD_APPROVED: Yes; FPLIST: RC0402_25,RC0402_HD,0402_CC; HEIGHT: 0.40 MM; MFG_NAME01: KOA SPEER; MFG_PN01: RK73H1ETTP2700F; ROHS: Yes; Temp Range: -55°C to +155°C; Temp_Range: -55°C to +155°C; Tolerance: 1%
R70 = RES: RES MF 10 OHM 1/10W 5% 0603; AGILE_PN: 470-75847; ASSY_OPT: DNP; CAD_APPROVED: Yes; FPLIST: RC0603_OV,RC0603,0603_CC; HEIGHT: 0.55MM; MFG_NAME01: VISHAY INTERTECHNOLOGY; MFG_PN01: CRCW060310R0JNEAC; ROHS: Yes; Tolerance: 5%; VOLTAGE: 50V
R71 = RES: RES MF ZERO OHM 1/16W 5% 0402; AGILE_PN: 470-75394; ASSY_OPT: DNP; CAD_APPROVED: Yes; FPLIST: RC0603_OV,RC0603,R603-X2,0603_CC; HEIGHT: 0.45 MM; MFG_NAME01: YAGEO AMERICA; MFG_PN01: RC0402JR-070RL; PRIORITY_PN: 006-00559; ROHS: Yes; SIGNAL_MODEL: DEFAULT_RESISTOR_0.001OHM_2_1; Tolerance: 5%; VOLTAGE: 1/16W
R10 R13 R25 R30 R48 R49 R59 R72 R75 R76 R79 R81 R84 R85 R88 R89 R92 R94 R96 R97 R100 R102 = RES: RES MF ZERO OHM 1/16W 5% 0402; AGILE_PN: 470-75394; CAD_APPROVED: Yes; FPLIST: RC0402_25,RC0402_HD,RC0402_X2,0402_CC; HEIGHT: 0.45 MM; MFG_NAME01: YAGEO AMERICA; MFG_PN01: RC0402JR-070RL; ROHS: Yes; Tolerance: 5%; VOLTAGE: 1/16W
R38 R39 R73 R74 R77 R78 R80 R82 R86 R87 R90 R91 R93 R95 R98 R99 R101 R103 = RES: RES MF ZERO OHM 1/16W 5% 0402; AGILE_PN: 470-75394; ASSY_OPT: DNP; CAD_APPROVED: Yes; FPLIST: RC0402_25,RC0402_HD,RC0402_X2,0402_CC; HEIGHT: 0.45 MM; MFG_NAME01: YAGEO AMERICA; MFG_PN01: RC0402JR-070RL; ROHS: Yes; Tolerance: 5%; VOLTAGE: 1/16W
R83 = RES: RES MF 10.0K 1/16W 1% AEC-Q200 0402; AGILE_PN: 470-75416; ASSY_OPT: DNP; CAD_APPROVED: Yes; FPLIST: RC0402_25,RC0402_HD,0402_CC; HEIGHT: 0.4MM; MFG_NAME01: KOA SPEER; MFG_PN01: RK73H1ETTP1002F; ROHS: Yes; SIGNAL_MODEL: DEFAULT_RESISTOR_10000OHM_2_1; TOL: 5%; Temp Range: –55 °C to +155 °C; Tolerance: 1%
TP1-TP18 TP20 = TESTLOOP: TEST POINT PAD 30MIL DIA SMT, NO PART TO ORDER; 3D_Mechanical_Footprint_File: ftp://fcl.am.freescale.net/ALLEGRO/step/tpad_030.STEP; AGILE_PN: 211-76642; CAD_APPROVED: Yes; HEIGHT: 0.1MM; MFG_NAME01: NOTACOMPONENT; MFG_PN01: NOTACOMPONENT; ROHS: Yes
TP19 = TESTLOOP: TEST POINT WHITE 40 MIL DRILL 180 MIL TH 109L; AGILE_PN: 210-75685; CAD_APPROVED: Yes; HEIGHT: 4.8 MM; MFG_NAME01: KEYSTONE ELECTRONICS; MFG_PN01: 5002; ROHS: Yes; Temp Range: -50°C to +146°C
U14 = LD1117AS18: IC VREG LDO 1A 3.3V SOT223; AGILE_PN: 312-80039; CAD_APPROVED: Yes; HEIGHT: 1.8MM; MFG_NAME01: ON SEMICONDUCTOR; ROHS: Yes; Temp Range: 0°C to +125°C; VOLTAGE: 3.3V
C1 C6 = CAP_NP: CAP CER 0.10UF 25V 10% X7R 0603; AGILE_PN: 150-75016; CAD_APPROVED: Yes; FPLIST: CC0603_OV,CC0603,0603_CC; HEIGHT: 0.97 MM; MFG_NAME01: KEMET; MFG_PN01: C0603C104K3RAC; Package Size: 0603; Package Type: 7; ROHS: Yes; TOL: 10%; Tolerance: 10%; VOLTAGE: 25V
C2-C5 C12 C13 C15 C16 C23-C31 C33 C43 C44 C49 C50 = CAP_NP: CAP CER 0.1UF 10V 10% X5R 0402; AGILE_PN: 150-75634; CAD_APPROVED: Yes; FPLIST: CC0402_25,CC0402_HD,0402_CC; HEIGHT: 0.64MM; MFG_NAME01: YAGEO AMERICA; MFG_PN01: CC0402KRX5R6BB104; Package Size: 0402; ROHS: Yes; TOL: 10%; Tolerance: 10%; VOLTAGE: 10V
C7-C11 = CAP_NP: CAP CER 220PF 50V 5% C0G 0402; AGILE_PN: 150-30297; CAD_APPROVED: Yes; FPLIST: CC0402_25,CC0402_HD,0402_CC,capc0402_l; HEIGHT: 0.55MM; MFG_NAME01: KEMET; MFG_PN01: C0402C221J5GAC; Package Size: 0402; ROHS: Yes; Tolerance: 5%; VOLTAGE: 50V
R1-R5 = RES: RES MF 100 OHM 1/16W 5% 0402; AGILE_PN: 470-75591; CAD_APPROVED: Yes; FPLIST: RC0402_25,RC0402_HD,RC0402_X2,0402_CC; HEIGHT: 0.45mm; MFG_NAME01: NIC COMPONENTS CORP; MFG_PN01: NRCL04J101TRF; ROHS: Yes; TOL: 1%; Tolerance: 5%
U1 = MKE17Z256VLL7: IC MCU 256K FLASH 72MHZ 2.7-5.5V LQFP100; 3D_Mechanical_Footprint_File: ftp://fcl.am.freescale.net/ALLEGRO/step/LQFP100_0P5_14X14.STEP; AGILE_PN: TMP-CIP-6345; CAD_APPROVED: Yes; HEIGHT: 1.7MM; MFG_NAME01: NXP SEMICONDUCTORS; PRE_APN: 344-02466; Package Size: 14x14x1.7 mm; ROHS: Yes; VOLTAGE: 2.7-5.5V
C17 = CAP_NP: CAP CER 1.0UF 10V 10% X5R 0402; AGILE_PN: 150-75772; CAD_APPROVED: Yes; FPLIST: CC0402_25,CC0402_HD,0402_CC; HEIGHT: 0.6MM; MFG_NAME01: YAGEO AMERICA; MFG_PN01: CC0402KRX5R6BB105; Package Size: 0402; ROHS: Yes; VOLTAGE: 10V
C18 = CAP_NP: CAP CER 1000PF 50V 5% C0G 0402; AGILE_PN: 150-76334; CAD_APPROVED: Yes; FPLIST: CC0402_25,CC0402_HD,0402_CC; HEIGHT: 0.55MM; MFG_NAME01: MURATA; MFG_PN01: GRM1555C1H102JA01D; Package Size: 0402; Package Type: 180mm Paper Tape; ROHS: Yes; Tolerance: 5%; VOLTAGE: 50V
C20 C21 = CAP_NP: CAP CER 22PF 50V 5% C0G 0402; AGILE_PN: 150-75266; ASSY_OPT: DNP; CAD_APPROVED: Yes; FPLIST: CC0402_25,CC0402_HD,0402_CC; HEIGHT: 0.635MM; MFG_NAME01: WURTH ELEKTRONIK EISOS GMBH & CO. KG (ELECTRONIC & ELECTROMEHANICAL COMP); MFG_PN01: 885012005057; ROHS: Yes; Temp Range: -55°C to 125°C; Tolerance: 5%; VOLTAGE: 50V
C32 = CAP_NP: CAP CER 18pF 25V 5% C0G 0402; AGILE_PN: 150-78760; ASSY_OPT: DNP; CAD_APPROVED: Yes; FPLIST: CC0402_25,CC0402_HD,0402_CC; HEIGHT: 0.56MM; MFG_NAME01: AVX; MFG_PN01: 04023A180JAT2A; ROHS: Yes; Tolerance: 5%; VOLTAGE: 25V
D1 = LED: LED ULTRA BRIGHT RED SGL 30MA 0603; AGILE_PN: 370-75079; CAD_APPROVED: Yes; HEIGHT: 0.9MM; MFG_NAME01: LITE ON; MFG_PN01: LTST-C190KRKT; ROHS: Yes; Rated Voltage: 2V; Temp Range: -30° C to + 85° C; VOLTAGE: 2V
D2 = LED: LED ULTRA-BRIGHT YELLOW 30MA 5V SMT 0603; AGILE_PN: 370-75076; CAD_APPROVED: Yes; HEIGHT: 0.8MM; MFG_NAME01: LITE ON; MFG_PN01: LTST-C190KSKT; ROHS: Yes
J6 = MICRO_USB_CONN_9PIN: CON 5 USB2.0 MICRO-AB RA SKT SMT 0.65MM SP AU; 3D_Mechanical_Footprint_File: ftp://fcl.am.freescale.net/ALLEGRO/step/micro_usb_conn_9pin.step; AGILE_PN: 211-77482; CAD_APPROVED: Yes; HEIGHT: 2.65MM; MFG_NAME01: HIROSE; MFG_PN01: ZX62-AB-5PA(31); ROHS: Yes
J8 J9 = CONN_HDR_2X1: HDR 1X2 TH 100MIL SP 339H AU 98L; 3D_Mechanical_Footprint_File: ftp://fcl.am.freescale.net/ALLEGRO/step/hdr102_95l.STEP; AGILE_PN: 210-81490; CAD_APPROVED: Yes; HEIGHT: 8.59MM; MFG_NAME01: ANYTRONIC CORPORATION LIMITED; MFG_PN01: 0901S0202011N9T-31RF; ROHS: Yes; Temp Range: -55°C to +105°C; Temp_Range: -55°C to +105°C
J11 J14 = CONN_HDR_5X2: HDR 2X5 TH 50MIL CTR 167H AU 91L; AGILE_PN: 210-80192; CAD_APPROVED: Yes; FPLIST: hdr_5X2_ftsh_th,hdr_5X2_ftsh_th_nsp; HEIGHT: 4.25MM; MFG_NAME01: ANYTRONIC CORPORATION LIMITED; MFG_PN01: 0922S0205011N6T-2LF; ROHS: Yes
L1 L2 = BEAD: IND FER BEAD 330OHM@100MHZ 2.5A -- SMT; 3D_Mechanical_Footprint_File: ftp://fcl.am.freescale.net/ALLEGRO/step/ind_0805.STEP; AGILE_PN: 180-30021; CAD_APPROVED: YES; HEIGHT: 1.05 MM; MFG_NAME01: TDK; MFG_PN01: MPZ2012S331AT000; PART_TYPE: FERRITE; ROHS: Yes; Temp Range: -55°C to +125°C; Tolerance: 25%
R6 R7 R9 R11 R18 R21 R27 R31 = RES: RES MF 10.0K 1/16W 1% AEC-Q200 0402; AGILE_PN: 470-75416; CAD_APPROVED: Yes; FPLIST: RC0402_25,RC0402_HD,0402_CC; HEIGHT: 0.4MM; MFG_NAME01: KOA SPEER; MFG_PN01: RK73H1ETTP1002F; ROHS: Yes; TOL: 5%; Temp Range: –55 °C to +155 °C; Tolerance: 1%
R8 R19 R20 R28 R32 R52-R55 R58 R63 R68 = RES: RES MF 4.7K 1/16W 5% 0402; AGILE_PN: 470-75626; CAD_APPROVED: Yes; FPLIST: RC0402_25,RC0402_HD,0402_CC; HEIGHT: 0.41mm; MFG_NAME01: NIC COMPONENTS CORP; MFG_PN01: NRCL04J472TRF; ROHS: Yes; TOL: 1%; Tolerance: 5%
R12 = RES: RES MF 2.2K 1/16W 5% 0402; AGILE_PN: 470-75636; CAD_APPROVED: Yes; FPLIST: RC0402_25,RC0402_HD,0402_CC; HEIGHT: 0.4 MM; MFG_NAME01: BOURNS; MFG_PN01: CR0402-JW-222GLF; ROHS: Yes; Tolerance: 5%
R14 R15 = RES: RES MF 33.0 OHM 1/16W 1% 0402; AGILE_PN: 470-75790; CAD_APPROVED: Yes; FPLIST: RC0402_25,RC0402_HD,RC0402_X2,0402_CC; HEIGHT: 0.4MM; MFG_NAME01: THYE MING TECH CO LTD; MFG_PN01: CR-02FL6---33R; ROHS: Yes; Tolerance: 1%
R16 = RES: RES MF ZERO OHM 1/16W 5% 0402; AGILE_PN: 470-75394; ASSY_OPT: DNP; CAD_APPROVED: Yes; FPLIST: RC0402_25,RC0402_HD,RC0402_X2,0402_CC; HEIGHT: 0.45 MM; MFG_NAME01: YAGEO AMERICA; MFG_PN01: RC0402JR-070RL; ROHS: Yes; TOL: 5%; Tolerance: 5%; VOLTAGE: 1/16W
R17 R22 R37 = RES: RES MF 1.0K 1/16W 1% 0402; AGILE_PN: 470-76037; CAD_APPROVED: Yes; FPLIST: RC0402_25,RC0402_HD,RC0402_X2,0402_CC; HEIGHT: 0.4MM; MFG_NAME01: YAGEO AMERICA; MFG_PN01: RC0402FR-071KL; ROHS: Yes; TOL: 1%; Tolerance: 1%; VOLTAGE: 1/16W
R24 R34 R60 = RES: RES MF 10.0K 1/16W 1% AEC-Q200 0402; AGILE_PN: 470-75416; CAD_APPROVED: Yes; FPLIST: RC0402_25,RC0402_HD,0402_CC; HEIGHT: 0.4MM; MFG_NAME01: KOA SPEER; MFG_PN01: RK73H1ETTP1002F; ROHS: Yes; Temp Range: –55 °C to +155 °C; Tolerance: 1%
R26 R62 = RES: RES MF 4.7K 1/16W 5% 0402; AGILE_PN: 470-75626; ASSY_OPT: DNP; CAD_APPROVED: Yes; FPLIST: RC0402_25,RC0402_HD,0402_CC; HEIGHT: 0.41mm; MFG_NAME01: NIC COMPONENTS CORP; MFG_PN01: NRCL04J472TRF; ROHS: Yes; TOL: 1%; Tolerance: 5%
R29 R61 = RES: RES MF 10.0K 1/16W 1% AEC-Q200 0402; AGILE_PN: 470-75416; ASSY_OPT: DNP; CAD_APPROVED: Yes; FPLIST: RC0402_25,RC0402_HD,0402_CC; HEIGHT: 0.4MM; MFG_NAME01: KOA SPEER; MFG_PN01: RK73H1ETTP1002F; ROHS: Yes; Temp Range: –55 °C to +155 °C; Tolerance: 1%
R33 = RES: RES MF 10.0K 1/16W 1% AEC-Q200 0402; AGILE_PN: 470-75416; ASSY_OPT: DNP; CAD_APPROVED: Yes; FPLIST: RC0402_25,RC0402_HD,0402_CC; HEIGHT: 0.4MM; MFG_NAME01: KOA SPEER; MFG_PN01: RK73H1ETTP1002F; ROHS: Yes; TOL: 1%; Temp Range: –55 °C to +155 °C; Tolerance: 1%
R35 = RES: RES MF 15K  1/16W 1% 0402; AGILE_PN: 470-30965; CAD_APPROVED: Yes; FPLIST: RC0402_25,RC0402_HD,0402_CC; HEIGHT: 0.40 MM; MFG_NAME01: WALSIN TECHNOLOGY CORP.; MFG_PN01: WR04X1502FTL; ROHS: Yes; TOL: 1%; Tolerance: 1%
R36 = RES: RES MF 10.0K 1/16W 1% AEC-Q200 0402; AGILE_PN: 470-75416; CAD_APPROVED: Yes; FPLIST: RC0402_25,RC0402_HD,0402_CC; HEIGHT: 0.4MM; MFG_NAME01: KOA SPEER; MFG_PN01: RK73H1ETTP1002F; ROHS: Yes; TOL: 1%; Temp Range: –55 °C to +155 °C; Tolerance: 1%
SH1 = RES_SHORT-2: ZERO OHM CUT TRACE 0603 PADS; NO PART TO ORDER; AGILE_PN: 470-80018; CAD_APPROVED: Yes; FPLIST: SH0603,SH0603_CC,SH0603-X2_PIN1TO2,SH0603-X2_PIN2TO3; HEIGHT: 0.1MM; ROHS: Yes
SW1-SW3 = SW2P_SPST: SW SPST PB 50MA 12V SMT; AGILE_PN: 510-77720; CAD_APPROVED: Yes; FPLIST: sw2_spst_4x3_sm,sw2_spst_4x3_sm_f; HEIGHT: 2.4MM; MFG_NAME01: E SWITCH; ROHS: Yes
U2 U11 U13 = NTSX2102GD: IC DUAL SUPPLY XCVR 50 MBPS 5.5V XQFN8; AGILE_PN: 312-80763; CAD_APPROVED: Yes; HEIGHT: 0.5MM; MFG_NAME01: NXP SEMICONDUCTORS; ROHS: Yes; VOLTAGE: 5.5V
U3 = PK20DX128V_QFN_32P: IC MCU FLASH 128KB 50MHZ 1.71-3.6V QFN32; AGILE_PN: 344-01231; CAD_APPROVED: Yes; HEIGHT: 1MM; MFG_NAME01: FREESCALE SEMICONDUCTOR; ROHS: Yes; VOLTAGE: 1.71-3.6V
U4 = NL27WZ14_6P: IC INV DUAL SCHMITT TRIGGER 1.65-5.5V UDFN6; AGILE_PN: 315-82857; CAD_APPROVED: Yes; HEIGHT: 0.55 MM; MFG_NAME01: ON SEMICONDUCTOR; ROHS: Yes; Temp Range: -55°C to +125°C; VOLTAGE: 1.65-5.5V
U5 = RCLAMP1654P_NEW: DIODE TVS ARRAY 3 5.5V SLP1616P6; AGILE_PN: 480-78843; CAD_APPROVED: Yes; HEIGHT: 0.65MM; MFG_NAME01: SEMTECH CORP; ROHS: Yes; VOLTAGE: 5.5V
U6 U8 U9 = 74LVCH1T45_6P: IC XCVR 1BIT 3-STATE DUAL 1.2-5.5V XSON6; AGILE_PN: 312-80758; CAD_APPROVED: Yes; HEIGHT: 0.5MM; MFG_NAME01: NEXPERIA; MFG_PN01: 74LVCH1T45GM,132; ROHS: Yes; VOLTAGE: 1.2-5.5V
U7 = 74LVC2T45GM_8P: IC XCVR DUAL SUPPLY 1.2 -5.5V XQFN8; AGILE_PN: 312-80762; CAD_APPROVED: Yes; HEIGHT: 0.5MM; MFG_NAME01: NEXPERIA; ROHS: Yes; VOLTAGE: 5.5V
U10 = MIC2005-0.8YM6: IC LIN SW PWR 0.8A 2.5-5.5V SOT23-6; AGILE_PN: 315-79199; CAD_APPROVED: Yes; HEIGHT: 1.45MM; MFG_NAME01: MICREL; ROHS: Yes; VOLTAGE: 2.5-5.5V
X1 = XTAL_CS: XTAL 8.00MHZ RSN CERAMIC -- SMT; AGILE_PN: 230-78262; CAD_APPROVED: Yes; HEIGHT: 0.8 MM; MFG_NAME01: MURATA; MFG_PN01: CSTNE8M00G550000R0; ROHS: Yes; Temp Range: -40 to +85°C
C34 C37 = CAP_NP: CAP CER 22PF 50V 5% C0G 0402; AGILE_PN: 150-75266; CAD_APPROVED: Yes; FPLIST: CC0402_25,CC0402_HD,0402_CC; HEIGHT: 0.635MM; MFG_NAME01: WURTH ELEKTRONIK EISOS GMBH & CO. KG (ELECTRONIC & ELECTROMEHANICAL COMP); MFG_PN01: 885012005057; ROHS: Yes; Temp Range: -55°C to 125°C; Tolerance: 5%; VOLTAGE: 50V
C36 C38 = CAP_NP: CAP CER 2200PF 50V 10%  X7R 0402; AGILE_PN: 150-75600; CAD_APPROVED: Yes; FPLIST: CC0402_25,CC0402_HD,0402_CC; HEIGHT: 0.56 MM; MFG_NAME01: AVX; MFG_PN01: 04025C222KAT2A; ROHS: Yes; Tolerance: 10%; VOLTAGE: 50V
C39 C40 = CAP_NP: CAP CER 22pF 50V 1% C0G 0402; AGILE_PN: 150-79491; ASSY_OPT: DNP; CAD_APPROVED: Yes; FPLIST: CC0402_25,CC0402_HD,0402_CC; HEIGHT: 0.56MM; MFG_NAME01: AVX; MFG_PN01: 04025A220FAT2A; Package Size: 0402; ROHS: Yes; Tolerance: 1%; VOLTAGE: 50V
C45 = CAP_NP: CAP CER 4.7UF 6.3V 20% X5R 0402; AGILE_PN: 150-78463; CAD_APPROVED: Yes; FPLIST: CC0402_25,CC0402_HD,0402_CC; HEIGHT: 0.65MM; MFG_NAME01: TDK; MFG_PN01: C1005X5R0J475M; ROHS: Yes; Tolerance: 20%; VOLTAGE: 6.3V
D3 = CLV1A_LED_4P: LED RED BL GRN SGL 50/25/25mA SMT; AGILE_PN: 370-76799; CAD_APPROVED: Yes; HEIGHT: 2.1MM; MFG_NAME01: CREE, INC; Temp Range: -40°C to 85°C; VOLTAGE: 5V
E1 E2 = ELECTRODE: CAPACITIVE SINGLE ELECTRODE 8MM SQUARE ROUNDED CORNERS, NO PART TO ORDER; AGILE_PN: 510-78043; CAD_APPROVED: Yes; HEIGHT: 0.1MM; MFG_NAME01: NA; MFG_PN01: NO PART TO ORDER1; ROHS: Yes
R40 R47 = RES: RES MF 4.99K 1/10W 1% 0603; AGILE_PN: 470-75771; CAD_APPROVED: Yes; FPLIST: RC0603_OV,RC0603,0603_CC; HEIGHT: 0.55MM; MFG_NAME01: BOURNS; MFG_PN01: CR0603-FX-4991ELF; ROHS: Yes; Tolerance: 1%
R41 = RES: RES MF 430 OHM 1/10W 1% AEC-Q200 0402; AGILE_PN: 470-30801; CAD_APPROVED: Yes; FPLIST: RC0402_25,RC0402_HD,0402_CC; HEIGHT: 0.40 MM; MFG_NAME01: KOA SPEER; MFG_PN01: RK73H1ETTP4300F; ROHS: Yes; Temp Range: -55C to +155C; Temp_Range: -55C to +155C; Tolerance: 1%; VOLTAGE: 50V
R44 R46 = RES: RES MF 100 OHM 1/16W 1% 0402; AGILE_PN: 470-30454; CAD_APPROVED: Yes; FPLIST: RC0402_25,RC0402_HD,0402_CC; HEIGHT: 0.4 MM; MFG_NAME01: THYE MING TECH CO LTD; MFG_PN01: CR-02FL6--100R; ROHS: Yes; Tolerance: 1%; VOLTAGE: 50V
R45 = RES: RES MF 1M 1/16W 1% 0402; AGILE_PN: 470-80575; ASSY_OPT: DNP; CAD_APPROVED: Yes; FPLIST: RC0402_25,RC0402_HD,0402_CC; HEIGHT: 0.4MM; MFG_NAME01: BOURNS; MFG_PN01: CR0402-FX-1004GLF; ROHS: Yes; Tolerance: 1%
R50 R51 R64-R67 = RES: RES MF 10.0K 1/16W 1% AEC-Q200 0402; AGILE_PN: 470-75416; CAD_APPROVED: Yes; FPLIST: RC0402_25,RC0402_HD,0402_CC; HEIGHT: 0.4MM; MFG_NAME01: KOA SPEER; MFG_PN01: RK73H1ETTP1002F; ROHS: Yes; SIGNAL_MODEL: DEFAULT_RESISTOR_10000OHM_2_1; TOL: 5%; Temp Range: –55 °C to +155 °C; Tolerance: 1%
R56 R57 = RES: RES MF ZERO OHM 1/10W -- AEC-Q200 0603; AGILE_PN: 470-75407; CAD_APPROVED: Yes; FPLIST: RC0603_OV,RC0603,R603-X2,0603_CC; HEIGHT: 0.6MM; MFG_NAME01: PANASONIC; MFG_PN01: ERJ-3GEY0R00V; ROHS: Yes; Temp Range: –55 °C to +155 °C; Tolerance: 1%; VOLTAGE: 1/10W
RT1 = THERMISTOR: THERMISTOR 10K 1/10W 1% 0603; AGILE_PN: 470-80022; CAD_APPROVED: Yes; FPLIST: RC0603_OV,RC0603,0603_CC; HEIGHT: 0.33MM; MFG_NAME01: MuRata; MFG_PN01: NCP18XH103F03RB; ROHS: Yes; Tolerance: 1%
U12 = FXOS8700CQ_QFN_16P: OBSOLETE IC ACCELEROMETER AND MAGNETOMETER SENSOR 3-AXIS 2.5V QFN16; AGILE_PN: 312-80418; ASSY_OPT: DNP; CAD_APPROVED: Yes; HEIGHT: 1.25MM; MFG_NAME01: FREESCALE SEMICONDUCTOR; ROHS: Yes; VOLTAGE: 2.5V
Y1 = XTAL_13: XTAL 8MHZ SER -- SMT; AGILE_PN: 230-77888; CAD_APPROVED: Yes; HEIGHT: 1.1MM; MFG_NAME01: DIODES INC; MFG_PN01: FY0800027; ROHS: Yes

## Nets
GND: C1.2 C2.2 C3.2 C4.2 C5.2 C6.2 C7.2 C8.2 C9.2 C10.2 C11.2 C12.2 C13.2 C14.2 C15.2 C16.2 C17.2 C18.2 C19.2 C20.2 C21.2 C22.2 C23.2 C24.2 C25.2 C26.2 C27.2 C28.2 C29.2 C30.2 C31.2 C33.2 C34.2 C36.2 C37.1 C38.2 C39.2 C40.2 C41.2 C42.2 C43.2 C44.2 C45.2 C46.2 C47.2 C48.2 C49.2 C50.2 C51.2 C52.2 C53.2 C54.2 C55.2 C56.2 C58.2 C59.2 C60.2 C61.2 C62.2 C63.2 D8.C(CATHODE) J2.14 J3.12(B6) J3.14(B7) J6.5(GND) J11.3(A2) J11.5(A3) J14.3(A2) J14.5(A3) J15.2 J15.3 J19.2 J20.2 L2.2 L5.1 R18.2 R24.2 R27.2 R29.2 R31.2 R35.2 R47.2 R62.2 R63.2 R74.1 SW1.1(SW1) SW2.2(SW2) SW3.2(SW2) TP17.1(Pin1) TP18.1(Pin1) TP19.1(Pin1) TP20.1(Pin1) U1.13(VREFL) U1.14(VSS1) U1.37(VSS2) U1.60(VSS3) U1.86(VSS4) U2.4(GND) U3.2(VSS1) U3.8(VSSA) U3.33(EPAD) U4.2(GND) U5.7(GND) U6.2(GND) U7.3(DIR) U7.4(GND) U8.2(GND) U9.2(GND) U10.2(GND) U11.4(GND) U12.3(RSVD1) U12.5(GND1) U12.12(GND2) U12.13(RSVD2) U13.4(GND) U14.1(GND) X1.2 Y1.2 Y1.4
P3V3: C44.1 C45.1 C46.1 C47.1 C50.1 D7.C J3.8(B4) J16.1 J18.3 R54.2 R55.2 R60.1 R61.1 R64.1 R67.1 U11.8(VCCB) U12.1(VDDIO) U12.14(VDD) U13.8(VCCB)
P3V3_SDA: C12.1 C13.1 C14.1 C15.1 C17.1 C23.1 C25.1 C27.1 C29.1 C33.1 J10.1 J11.1(A1) R6.1 R8.1 R9.1 R11.2 R19.1 R23.1 R28.1 R32.1 R34.1 R36.1 U2.1(VCCA) U3.1(VDD1) U3.7(VDDA) U3.11(VBAT) U4.5(VCC) U6.1(VCCA) U7.7(VCCA) U8.1(VCCA) U9.1(VCCA)
P3V3_VREG: C53.1 D7.A J16.2 U14.2(VOUT) U14.4(TAB)
P5V0_SDA_USB_CONN_VBUS: J6.1(VBUS) L1.1 U5.6(VBUS)
P5V_LDO_OUT: C63.1 D5.A D10.A J20.3
P5V_SDA: C19.1 C31.1 C32.1 L1.2 R20.1 R26.1 R33.1 U3.6(VREGIN) U10.1(VIN)
P5V_SDA_PSW: D6.A D9.A U10.6(VOUT)
VDD: C43.1 C49.1 C58.1 C59.1 D3.2(COMMON_A) J3.4(B2) J17.1 J18.2 J19.1 R50.1 R51.1 R52.2 R53.2 R58.1 R65.1 R66.1 R68.1 R69.1 R70.1 R83.1 SH1.2 U11.1(VCCA) U13.1(VCCA)
VDD_5V: C52.1 D4.C D5.C D6.C J18.1 U14.3(VIN)
VDD_KE17Z: C2.1 C3.1 C4.1 C5.1 C54.1 C55.1 J14.1(A1) J17.2 L3.1 R70.2 U1.10(VDD1) U1.38(VDD2) U1.61(VDD3) U1.87(VDD4)
VDDA: C1.1 C56.1 J12.2 L3.2 L4.1 U1.11(VDDA)
AREF: J2.16 R71.2
BYP_FXOS8700CQ: C51.1 U12.2(BYP)
CRST_FXOS8700CQ: C48.1 U12.8(CRST)
DC_JACK_5V_INPUT: D4.A J15.1(Pin)
FXOS_INT: R59.2 R64.2 U13.7(B1)
FXOS_RST: R67.2 U12.16(RST) U13.6(B2)
FXOS_SCL: R55.1 R56.2 U11.7(B1)
FXOS_SDA: R54.1 R57.2 U11.6(B2)
I2C_SCL_FXOS8700CQ: R56.1 U12.4(SCL/SCLK)
I2C_SDA_FXOS8700CQ: R57.1 U12.6(SDA/MOSI)
INT1_FXOS8700CQ_R: R59.1 U12.11(INT1)
LEDRGB_BLUE: D3.3(BLUE_C) R43.1
LEDRGB_GREEN: D3.4(GREEN_C) R42.1
LEDRGB_RED: D3.1(RED_C) R41.2
LVLRST_EN: R8.2 U2.5(OE)
MIC2005_CSLEW: C32.2 U10.5(CSLEW)
P5-9V_VIN: C60.1 C61.1 C62.1 J3.16(B8) J20.1
POWER_EN: R37.1 U3.31(ADC0_SE7B/PTD6/SPI0_PCS3/UART0_RX/FTM0_CH6/FTM0_FLT0/LLWU_P15)
PTA0: J4.12(B6) U1.79(PTA0/ACMP0_IN0/TSI1_CH2/FTM2_CH1/LPI2C0_SCLS/FXIO_D2/LPUART0_CTS/TRGMUX_OUT3)
PTA1: J4.10(B5) U1.78(PTA1/ACMP0_IN1/TSI1_CH3/FTM1_CH1/LPI2C0_SDAS/FXIO_D3/LPUART0_RTS/TRGMUX_OUT0)
PTA2: R77.1 U1.73(PTA2/TSI1_CH4/LPI2C0_SDA/~{EWM_OUT}/LPUART0_RX)
PTA3: R78.1 U1.72(PTA3/TSI1_CH5/LPI2C0_SCL/EWM_IN/LPUART0_TX)
PTA4: J8.1 J14.2(B1) U1.98(PTA4/LPUART1_TX/ACMP0_OUT/~{EWM_OUT}/SWD_DIO)
PTA5: D1.C(CATHODE) J3.6(B3) J5.3 J14.10(B5) R7.2 R16.2 U1.97(PTA5/TCLK1/~{RESET}) U2.7(B1)
PTA6: R101.1 U1.58(PTA6/TSI1_CH11/FTM0_FLT1/LPUART1_CTS)
PTA7: R73.1 U1.57(PTA7/TSI1_CH12/FTM0_FLT2/LPSPI0_PCS3/LPUART1_RTS)
PTA8: J1.5(A3) U1.100(PTA8/FXIO_D6/TRGMUX_OUT0)
PTA9: J1.7(A4) U1.99(PTA9/FXIO_D7/TRGMUX_OUT1)
PTA10: R76.1 U1.92(PTA10/TSI0_CH5/LPUART0_TX/FXIO_D0)
PTA11: R75.1 U1.91(PTA11/TSI0_CH4/LPUART0_RX/FXIO_D1)
PTA12: R87.1 U1.90(PTA12/TSI0_CH3/LPUART0_TX)
PTA13: R86.1 U1.89(PTA13/TSI0_CH2/LPUART0_RX)
PTA14: J1.16(B8) U1.88(PTA14/FTM0_FLT0/EWM_IN/BUSOUT)
PTA15: J1.12(B6) U1.83(PTA15/FTM1_CH2/LPSPI0_PCS3)
PTA16: J2.18 R52.1 U1.82(PTA16/FTM1_CH3/LPI2C0_SDA) U11.3(A2)
PTA17: J1.14(B7) U1.62(PTA17/FTM0_CH6/~{EWM_OUT})
PTB0: R17.2 U1.54(PTB0/TSI1_CH15/LPUART0_RX/LPSPI0_PCS0/LPTMR0_ALT3/PWT_IN3)
PTB1: R21.2 R22.2 U1.53(PTB1/TSI1_CH16/LPUART0_TX/LPSPI0_SOUT/TCLK0)
PTB2: J2.12 U1.48(PTB2/TSI1_CH17/FTM1_CH0/LPSPI0_SCK/TRGMUX_IN3)
PTB3: J2.10 U1.47(PTB3/TSI1_CH18/FTM1_CH1/LPSPI0_SIN/TRGMUX_IN2)
PTB4: J2.8 U1.28(PTB4/ADC0_SE5/TSI0_CH24/FTM0_CH4/LPSPI0_SOUT/TRGMUX_IN1)
PTB5: J2.6 U1.27(PTB5/ADC0_SE3/TSI0_CH23/FTM0_CH5/LPSPI0_PCS1/TRGMUX_IN0)
PTB6: C34.1 R45.1 U1.16(PTB6/XTAL/LPI2C0_SDA/LPUART0_RX) Y1.3
PTB7: C37.2 R45.2 U1.15(PTB7/EXTAL/LPI2C0_SCL/LPUART0_TX) Y1.1
PTB8: J2.20 R53.1 U1.77(PTB8/LPI2C0_SCL/FXIO_D4) U11.2(A1)
PTB9: R66.2 U1.76(PTB9/LPI2C0_SCLS/FXIO_D5) U13.3(A2)
PTB10: R65.2 U1.75(PTB10/FTM0_CH0/LPI2C0_SDAS/FXIO_D0) U13.2(A1)
PTB11: J2.4 U1.74(PTB11/FTM0_CH1/LPI2C0_HREQ/FXIO_D1)
PTB12: J3.15(A8) U1.68(PTB12/TSI1_CH8/FTM0_CH0)
PTB13: J3.13(A7) U1.67(PTB13/TSI1_CH9/FTM0_CH1)
PTB14: J3.11(A6) U1.66(PTB14/FTM0_CH2)
PTB15: J3.9(A5) U1.65(PTB15/FTM0_CH3)
PTB16: J3.7(A4) U1.64(PTB16/FTM0_CH4)
PTB17: J3.5(A3) U1.63(PTB17/FTM0_CH5)
PTC0: C38.1 R46.1 U1.40(PTC0/ADC0_SE10/TSI1_CH23/FTM0_CH0)
PTC1: C36.1 R44.1 U1.39(PTC1/ADC0_SE8/TSI1_CH24/FTM0_CH1)
PTC2: C7.1 R1.2 U1.30(PTC2/ADC0_SE15/ACMP0_IN5/FTM0_CH2/FXIO_D6)
PTC2/MC_CUR_DCB: R1.1 R84.1
PTC3: C8.1 R2.2 U1.29(PTC3/ADC0_SE7/ACMP0_IN4/FTM0_CH3/FXIO_D7)
PTC3/MC_BEMF_B: R2.1 R89.1
PTC4: J13.1 U1.96(PTC4/ACMP0_IN2/FTM1_CH0/LPUART1_RX/EWM_IN/SWD_CLK)
PTC5: C40.1 R48.2 U1.95(PTC5/TSI0_CH8/FTM2_CH0)
PTC6: R95.1 U1.81(PTC6/TSI1_CH0/LPUART1_RX)
PTC7: R93.1 U1.80(PTC7/TSI1_CH1/LPUART1_TX)
PTC8: R99.1 U1.56(PTC8/TSI1_CH13/LPUART1_RX/LPUART0_CTS)
PTC9: R98.1 U1.55(PTC9/TSI1_CH14/LPUART1_TX/LPUART0_RTS)
PTC10: J1.9(A5) U1.52(PTC10/LPSPI0_SCK)
PTC11: J1.11(A6) U1.51(PTC11/LPSPI0_SIN)
PTC12: J1.13(A7) U1.50(PTC12/LPSPI0_SOUT)
PTC13: J1.15(A8) U1.49(PTC13/LPSPI0_PCS0)
PTC14: J1.10(B5) U1.46(PTC14/TSI1_CH19/FTM1_CH2)
PTC15: C39.1 R49.2 U1.45(PTC15/TSI1_CH20/FTM1_CH3)
PTC16: J4.4(B2) U1.44(PTC16/ADC0_SE14/TSI1_CH21)
PTC17: J4.2(B1) U1.43(PTC17/ADC0_SE12/TSI1_CH22)
PTD0: R72.1 U1.4(PTD0/TSI0_CH12/FTM0_CH2/FTM2_CH0/FXIO_D0/TRGMUX_OUT1)
PTD1: R100.1 U1.3(PTD1/TSI0_CH11/FTM0_CH3/FTM2_CH1/FXIO_D1/TRGMUX_OUT2)
PTD2: R80.1 U1.71(PTD2/TSI1_CH6/FXIO_D4/LPI2C0_SDA/TRGMUX_IN5)
PTD3: C41.1 R50.2 SW2.1(SW1) U1.70(PTD3/FXIO_D5/LPI2C0_SCL/TRGMUX_IN4/~{NMI})
PTD4: R82.1 U1.69(PTD4/TSI1_CH7/FTM0_FLT3)
PTD5: J3.1(A1) U1.33(PTD5/ADC0_SE9/FTM2_CH3/LPTMR0_ALT2/FXIO_D3/PWT_IN2/TRGMUX_IN7/LPUART2_CTS)
PTD6: C9.1 R3.2 U1.32(PTD6/ADC0_SE11/LPUART2_RX)
PTD6/MC_BEMF_A: J2.1 R3.1
PTD7: C10.1 R4.2 U1.31(PTD7/ADC0_SE13/LPUART2_TX)
PTD7/MC_VOLT_DCB: R4.1 R85.1
PTD8: J1.6(B3) U1.42(PTD8/FTM0_CH7/LPSPI0_PCS1)
PTD9: J1.8(B4) U1.41(PTD9/FXIO_D2)
PTD10: R41.1 U1.36(PTD10/FTM2_CH0)
PTD11: R42.2 U1.35(PTD11/FTM2_CH1/LPUART2_CTS)
PTD12: R43.2 U1.34(PTD12/FTM2_CH2/LPUART2_RTS)
PTD13: J19.4 U1.25(PTD13/LPUART1_RX)
PTD14: J19.3 R83.2 U1.24(PTD14/LPUART1_TX/CLKOUT)
PTD15: J4.8(B4) U1.22(PTD15/ADC0_SE2/TSI0_CH20/FTM0_CH0)
PTD16: J4.6(B3) U1.21(PTD16/ADC0_SE4/TSI0_CH19/FTM0_CH1)
PTD17: J1.2(B1) U1.20(PTD17/FTM0_FLT2/LPUART2_RX/TRGMUX_OUT2)
PTE0: R81.1 U1.94(PTE0/TSI0_CH7/LPSPI0_SCK/TCLK1)
PTE1: R79.1 U1.93(PTE1/TSI0_CH6/LPSPI0_SIN/LPI2C0_HREQ)
PTE2: R91.1 U1.85(PTE2/TSI0_CH1/LPSPI0_SOUT/LPTMR0_ALT3/PWT_IN3/LPUART1_CTS)
PTE3: J1.3(A2) U1.18(PTE3/ADC0_SE6/TSI0_CH18/FTM0_FLT0/LPUART2_RTS/TRGMUX_IN6)
PTE4: J1.1(A1) U1.9(PTE4/TSI0_CH17/BUSOUT/FTM2_CH2/FXIO_D6/~{EWM_OUT})
PTE5: R92.1 U1.8(PTE5/TSI0_CH16/TCLK2/FTM2_CH3/FXIO_D7/EWM_IN)
PTE6: R90.1 U1.84(PTE6/TSI0_CH0/LPSPI0_PCS2/LPUART1_RTS)
PTE7: R103.1 U1.59(PTE7/TSI1_CH10/FTM0_CH7)
PTE8: C11.1 R5.2 U1.26(PTE8/ACMP0_IN3/ADC0_SE1/TSI0_CH22/FTM0_CH6)
PTE8/MC_BEMF_C: R5.1 R88.1
PTE9: J3.3(A2) U1.23(PTE9/ADC0_SE0/TSI0_CH21/FTM0_CH7/LPUART2_CTS)
PTE10: R102.1 U1.6(PTE10/TSI0_CH10/CLKOUT/FXIO_D4/TRGMUX_OUT4)
PTE11: J2.2 U1.5(PTE11/TSI0_CH9/PWT_IN1/LPTMR0_ALT1/FXIO_D5/TRGMUX_OUT5)
PTE12: J1.4(B2) U1.19(PTE12/FTM0_FLT3/LPUART2_TX/TRGMUX_OUT3)
PTE13: R94.1 U1.7(PTE13/TSI0_CH15/TRGMUX_OUT5)
PTE14: C42.1 R51.2 SW3.1(SW1) U1.17(PTE14/FTM0_FLT1/TRGMUX_OUT4)
PTE15: R96.1 U1.2(PTE15/TSI0_CH14/FXIO_D2/TRGMUX_OUT6)
PTE16: R97.1 U1.1(PTE16/TSI0_CH13/FXIO_D3/TRGMUX_OUT7)
SA0_FXOS8700CQ: R61.2 R63.1 U12.7(SA0/MISO)
SA1_FXOS8700CQ: R60.2 R62.1 U12.10(SA1/~{CS})
SDA_EXTAL: C21.1 U3.17(EXTAL0/PTA18/FTM0_FLT2/FTM_CLKIN0) X1.3
SDA_JTAG_TCLK: J11.4(B2) U3.12(JTAG_TCLK/SWD_CLK/EZP_CLK/TSI0_CH1/PTA0/~{UART0_CTS}/~{UART0_COL}/FTM0_CH5)
SDA_JTAG_TDI: J11.8(B4) U3.13(JTAG_TDI/EZP_DI/TSI0_CH2/PTA1/UART0_RX/FTM0_CH6)
SDA_JTAG_TDO: J11.6(B3) U3.14(JTAG_TDO/TRACE_SWO/EZP_DO/TSI0_CH3/PTA2/UART0_TX/FTM0_CH7)
SDA_JTAG_TMS: J11.2(B1) R34.2 U3.15(JTAG_TMS/SWD_DIO/TSI0_CH4/PTA3/~{UART0_RTS}/FTM0_CH0)
SDA_LED: D2.C(CATHODE) TP12.1(Pin1) U3.29(PTD4/SPI0_PCS1/~{UART0_RTS}/FTM0_CH4/EWM_IN/LLWU_P14)
SDA_LED_R: D2.A(ANODE) R23.2
SDA_RST: J11.10(B5) R20.2 R24.1 TP10.1(Pin1) U3.19(~{RESET})
SDA_RST_LED: D1.A(ANODE) R12.1
SDA_RST_TGTMCU_B: J7.2 U3.21(ADC0_SE9/TSI0_CH6/PTB1/I2C0_SDA/FTM1_CH1/FTM1_QD_PHB)
SDA_RST_TGTMCU_J_B: J5.1 J7.1 R6.2 R16.1 U2.2(A1)
SDA_RX_EN: R18.1 R19.2 U6.5(DIR)
SDA_SPI0_CS: R39.2 TP8.1(Pin1) U3.23(ADC0_SE4B/CMP1_IN0/TSI0_CH15/PTC2/SPI0_PCS2/~{UART1_CTS}/FTM0_CH1/I2S0_TX_FS)
SDA_SPI0_RST_B: R38.2 TP7.1(Pin1) U3.22(ADC0_SE15/TSI0_CH14/PTC1/SPI0_PCS3/~{UART1_RTS}/FTM0_CH0/I2S0_TXD0/LLWU_P6)
SDA_SPI0_SCK: TP15.1(Pin1) U3.26(PTC5/SPI0_SCK/LPTMR0_ALT2/I2S0_RXD0/CMP0_OUT/LLWU_P9) U9.3(A)
SDA_SPI0_SIN: TP11.1(Pin1) U3.28(CMP0_IN1/PTC7/SPI0_SIN/USB_SOF_OUT/I2S0_RX_FS) U7.5(2A)
SDA_SPI0_SOUT: TP13.1(Pin1) U3.27(CMP0_IN0/PTC6/SPI0_SOUT/PDB0_EXTRG/I2S0_RX_BCLK/I2S0_MCLK/LLWU_P10) U8.3(A)
SDA_SWD_EN: R30.1 R38.1 U4.6(Y1)
SDA_SWD_EN_B: R10.2 U3.16(~{NMI}/~{EZP_CS}/TSI0_CH5/PTA4/FTM0_CH1/LLWU_P3)
SDA_SWD_EN_B_R: R9.2 R10.1 U4.1(A1)
SDA_SWD_EN_R: R30.2 R31.1 R32.2 U9.5(DIR)
SDA_SWD_OE: R25.1 R39.1 U4.4(Y2)
SDA_SWD_OE_B: R13.2 U3.20(ADC0_SE8/TSI0_CH0/PTB0/I2C0_SCL/FTM1_CH0/FTM1_QD_PHA/LLWU_P5)
SDA_SWD_OE_B_R: R11.1 R13.1 U4.3(A2)
SDA_SWD_OE_R: R25.2 R27.1 R28.2 U8.5(DIR)
SDA_USB_CONN_DN: J6.2(D-) R14.1 U5.1(DM)
SDA_USB_CONN_DP: J6.3(D+) R15.1 U5.2(DP)
SDA_USB_DN: R14.2 U3.4(USB0_DM)
SDA_USB_DP: R15.2 U3.3(USB0_DP)
SDA_USB_P5V_SENSE: R26.2 R29.1 TP14.1(Pin1) U3.30(ADC0_SE6B/PTD5/SPI0_PCS2/~{UART0_CTS}/~{UART0_COL}/FTM0_CH5/~{EWM_OUT})
SDA_USBSHIELD: J6.6(SHELL1) J6.7(SHELL2) J6.8(SHELL3) J6.9(SHELL4) L2.1
SDA_VOUT33: C22.1 J10.2 U3.5(VOUT33)
SDA_XTAL: C20.1 U3.18(XTAL0/PTA19/FTM1_FLT0/FTM_CLKIN1/LPTMR0_ALT1) X1.1
SW1_RST_B: C18.1 J5.2 SW1.2(SW2)
SWD_CLK_TGTMCU: J9.1 J13.2 J14.4(B2)
SWD_CLK_TGTMCU_BUF: J9.2 U9.4(B)
SWD_DIO_TGTMCU_BUF: J8.2 U7.2(2B) U8.4(B)
TC_EXTAL_TP: TP4.1(Pin1) U3.10(EXTAL32)
TC_SDA_USB_ID_TP: J6.4(ID) TP3.1(Pin1) U5.3(USB_ID)
TC_XTAL_TP: TP5.1(Pin1) U3.9(XTAL32)
THER_A: C35.1 R40.2 R44.2 RT1.1
THER_B: C35.2 R46.2 R47.1 RT1.2
TP_2102_A: TP2.1(Pin1) U2.3(A2)
TP_2102_B: TP1.1(Pin1) U2.6(B2)
TSI_ELECTRODE1: E1.1 R48.1
TSI_ELECTRODE2: E2.1 R49.1
UART0_RX_TGTMCU_BUF: R17.1 U6.4(B)
UART0_RX_TGTMCU_R: TP6.1(Pin1) U3.25(PTC4/SPI0_PCS0/UART1_TX/FTM0_CH3/CMP1_OUT/LLWU_P8) U6.3(A)
UART0_TX_TGTMCU_BUF: R22.1 U7.1(1B)
UART0_TX_TGTMCU_R: TP9.1(Pin1) U3.24(CMP1_IN1/PTC3/SPI0_PCS1/UART1_RX/FTM0_CH2/I2S0_TX_BCLK/LLWU_P7) U7.6(1A)
V_TGTMCU: C16.1 C24.1 C26.1 C28.1 C30.1 R7.1 R12.2 R21.1 SH1.1 U2.8(VCCB) U6.6(VCCB) U7.8(VCCB) U8.6(VCCB) U9.6(VCCB)
VREFH: C6.1 C57.1 L4.2 R71.1 U1.12(VREFH)
VREFL: C57.2 L5.2
VTRG_EN: R33.2 R35.1 R37.2 U10.3(ENABLE)
VTRG_FAULT_B: R36.2 TP16.1(Pin1) U3.32(PTD7/CMT_IRO/UART0_TX/FTM0_CH7/FTM0_FLT1) U10.4(~{FAULT})
N16603969: R58.2 U11.5(OE)
N16604691: R68.2 U13.5(OE)
N16623462: J2.19 R72.2 R73.2 R74.2
N16623486: J2.15 R76.2 R78.2
N16623490: J2.13 R79.2 R80.2
N16623494: J2.11 R81.2 R82.2
N16623498: J2.9 R84.2 R86.2
N16623502: J2.7 R85.2 R87.2
N16623506: J2.5 R88.2 R90.2
N16623510: J2.3 R89.2 R91.2
N16623816: J4.11(A6) R92.2 R93.2
N16623832: J4.9(A5) R94.2 R95.2
N16623848: J4.7(A4) R96.2 R98.2
N16623864: J4.5(A3) R97.2 R99.2
N16623880: J4.3(A2) R100.2 R101.2
N16623888: J4.1(A1) R102.2 R103.2
N16624332: D9.C D10.C J3.10(B5)
N16637975: J2.17 R75.2 R77.2
N16831370: D8.A(ANODE) R69.2
N16831714: J12.1 R40.1

Not connected (* = marked no-connect by the designer): J3 2(B1)*; J11 7(A4)* 9(A5)*; J14 6(B3)* 7(A4)* 8(B4)* 9(A5)*; U5 4(NC1)* 5(NC2)*; U12 9(INT2)* 15(NC)*

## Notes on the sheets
sheet 1
- Table of Contents
- Revisions
- 1
- Title Page
- Rev
- Description
- Date
- Approved
- 2
- Block Diagram
- X1
- Original Release
- 12/14/2020
- Jonson Chen
- 3
- KE17Z MCU
- A
- Release
- 03/02/2021
- Jonson Chen
- 4
- OpenSDA Interface
- U12 : DNP
  J7, J10, J13, J16:
  SHORTING HEADER ON BOTTOM LAYER
  MC_BEMF_A: PTD6/ADC0_SE11
  MC_CUR_DCB: PTC2/ADC0_SE15/ACMP0_IN5
- 5
- Touch & Sensor & Misc
- AX1
- 05/31/2021
- Jonson Chen
- 6
- I/O Headers & Power Supply
- B
- Release
- 05/31/2021
- Jonson Chen
- FREEDOM KE17Z
sheet 3
- CAD NOTE:
  Please place these capacitors
  near their respective CPU pin
  (VDD to VSS)
- KINETIS KE17Z MCU
- Pin Function Select
sheet 4
- OpenSDA Interface
- RESET
- 1-2: Default.
  2-3: Reset signal direct to the MCU,
  to use when OpenSDA is not powered.
- RST Push Button
  Bypass
- SHORTING HEADER
  ON BOTTOM LAYER
- MICRO-AB
- TARGET MCU
  INTERFACE
  SIGNALS
- Output to system
  from Level shifter
- Output to system
  from Level shifter
- Isolation
  Resistors
- Input to Level shifter
  from system
- * Default 1-2
- PU/PD LOGIC:
  SERIAL INTERFACE
  IS ALWAYS RESET
  WHEN USB PORT
  IS DISCONNECTED
- * Default 1-2
- OPEN SDA
  POWER OUTPUTS
- HW Designer: Rafael del Rey
- OPEN SDA
  INPUT POWER
- i
- path
- i
- path
- Note: You can power openSDA
  with your own power supplies
  by replacing this rail
  (SDA_VOUT33)
  with your 3.3V power supply rail
- 3.3VDC, 10mA should be provided
  to this rail (P3V3_SDA)
  in order to power openSDA
  module
- SHORTING HEADER ON BOTTOM LAYER
- PWR SWITCH
- SDA_VOUT33 can provide up to 120mA
  of power at 3.3VDC to your system
- OpenSDA INTERFACE JTAG CONNECTOR
- (To enable 5v from
  USB connector)
- Isolation and level shift stage
  (for 1.8 to 5V compatibility)
- PU/PD LOGIC (DIR PIN):
  BUFFER IS TRISTATED WHEN
  P3V3_SDA IS UNPOWERED
- i
- path
- P5V_SDA_PSW can provide up to 450mA
  (per USB spec) of power at 5VDC
  to your system
- ACTIVE HIGH
- I/O POWER
  INPUT
- i
- path
- This power rail is supported
  from 1.8V to 5V
- Power should be provided
  to this rail for the logic
  related to your platform I/O
- {For enablement purposes only}
sheet 5
- THERMISTOR
- External Crystal
- RGB LED
- Open this jumper
  for MCU current
  consumption test.
- 90C to -20C
- * Default 1-2
- Crystal8M_XTAL
- RGB_RED
- RGB_GREEN
- Vdiff ~ 0.372V to 2.879V
  (Ta=25C 1.650V)
- RGB_BLUE
- THERM_0
- THERM_1
- Crystal8M_EXTAL
- TSI TOUCH PAD
- INTERRUPT PUSH BUTTONS
- SHORTING HEADER ON BOTTOM LAYER
  Jumper is shorted by a cut-trace
  on bottom layer. Cutting the trace
  will effectively isolate the on-board
  MCU from the OpenSDA
  debug interface.
- TOUCH_PAD_0
- SWD CONNECTOR
- TOUCH_PAD_1
- NMI_b
- BUTTON_0
- Interrupt
- BUTTON_1
- FXOS8700CQ SENSOR
  ACCELEROMETER + MAGNETOMETER
- FXOS_SCL
- FXOS_SDA
- Voltage level-shift to be compatible with 5V and 3.3V
- Default I2C Slave Address:
        0011100 (0x1C)
- FXOS_INT
- FXOS_RST
sheet 6
- 3.3VDC Voltage Regulator
- ATTENTION!
  WHEN MCU IS 5V POWERED DIRECTLY, PLEASE MAKE SURE THE INPUT POWER SOURCE IS 5V.
- * Default 1-2
- 20mOhm
  Resistor in
  layout
- SHORTING HEADER
  ON BOTTOM LAYER
- 1-2: VDD = 5V Defult
  2-3: VDD = 3.3V
- Current here includes digital and analog
  (e.g. thermistor)
- 5VDC Power Supply
- Arduino_D0
- Arduino_D1
- Arduino_D2
- Arduino_D3
- Arduino_D4
- Arduino_D5
- Arduino_D6
- Arduino_D7
- Arduino_D8
- Arduino_D9
- Arduino_D10
- Arduino_D11
- Arduino_D12
- Arduino_D13
- GND
- AREF
- Arduino_D14
- Arduino_D15
- GND/GES_SHIELD
- BLUETOOTH HEADER
- IN CIRCUIT TEST
  GND PROBING
- TOUCH_M_TX_1/GES_R5
- DEBUG GROUND HOOK
- TOUCH_M_TX_0/GES_R4
- TOUCH_M_RX_1/GES_R3
- TOUCH_M_RX_0/GES_R2
- GES_R1/MC_CUR_DCB
- GES_R0/MC_VOLT_DCB
- BLUETOOTH_TX
- BLUETOOTH_RX
- MC_BEMF_C
- MC_BEMF_B
- MC_BEMF_A
- FREEDOM PLATFORM
  COMPATIBILITY HEADERS
- MC_ENC_I
- TOUCH_S_5/GES_C0
- TOUCH_S_4/GES_C1
- TOUCH_S_3/GES_C2
- TOUCH_S_2/GES_C3
- TOUCH_S_1/GES_C4
- TOUCH_S_0/GES_C5
- MC_PWM_AT
- MC_PWM_AB
- MC_PWM_BT
- MC_PWM_BB
- MC_PWM_CB
- MC_PWM_CT
- 5VDC LDO
  (e.g.7805)
- MC_ENC_A
- MC_ENC_B
- VIN
- VOUT
- Arduino_A0
- Arduino_A1
- Arduino_A2
- Arduino_A3
- Arduino_A4
- Arduino_A5
